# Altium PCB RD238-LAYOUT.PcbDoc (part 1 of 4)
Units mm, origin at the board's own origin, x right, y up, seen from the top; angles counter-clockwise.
Board outline 100 x 120 mm, 4 copper layers (Top Layer, GND2, POWER 3, Bottom Layer), stack 1.444 mm thick; 434 components, 174 nets, 1045 pads, 261 vias.
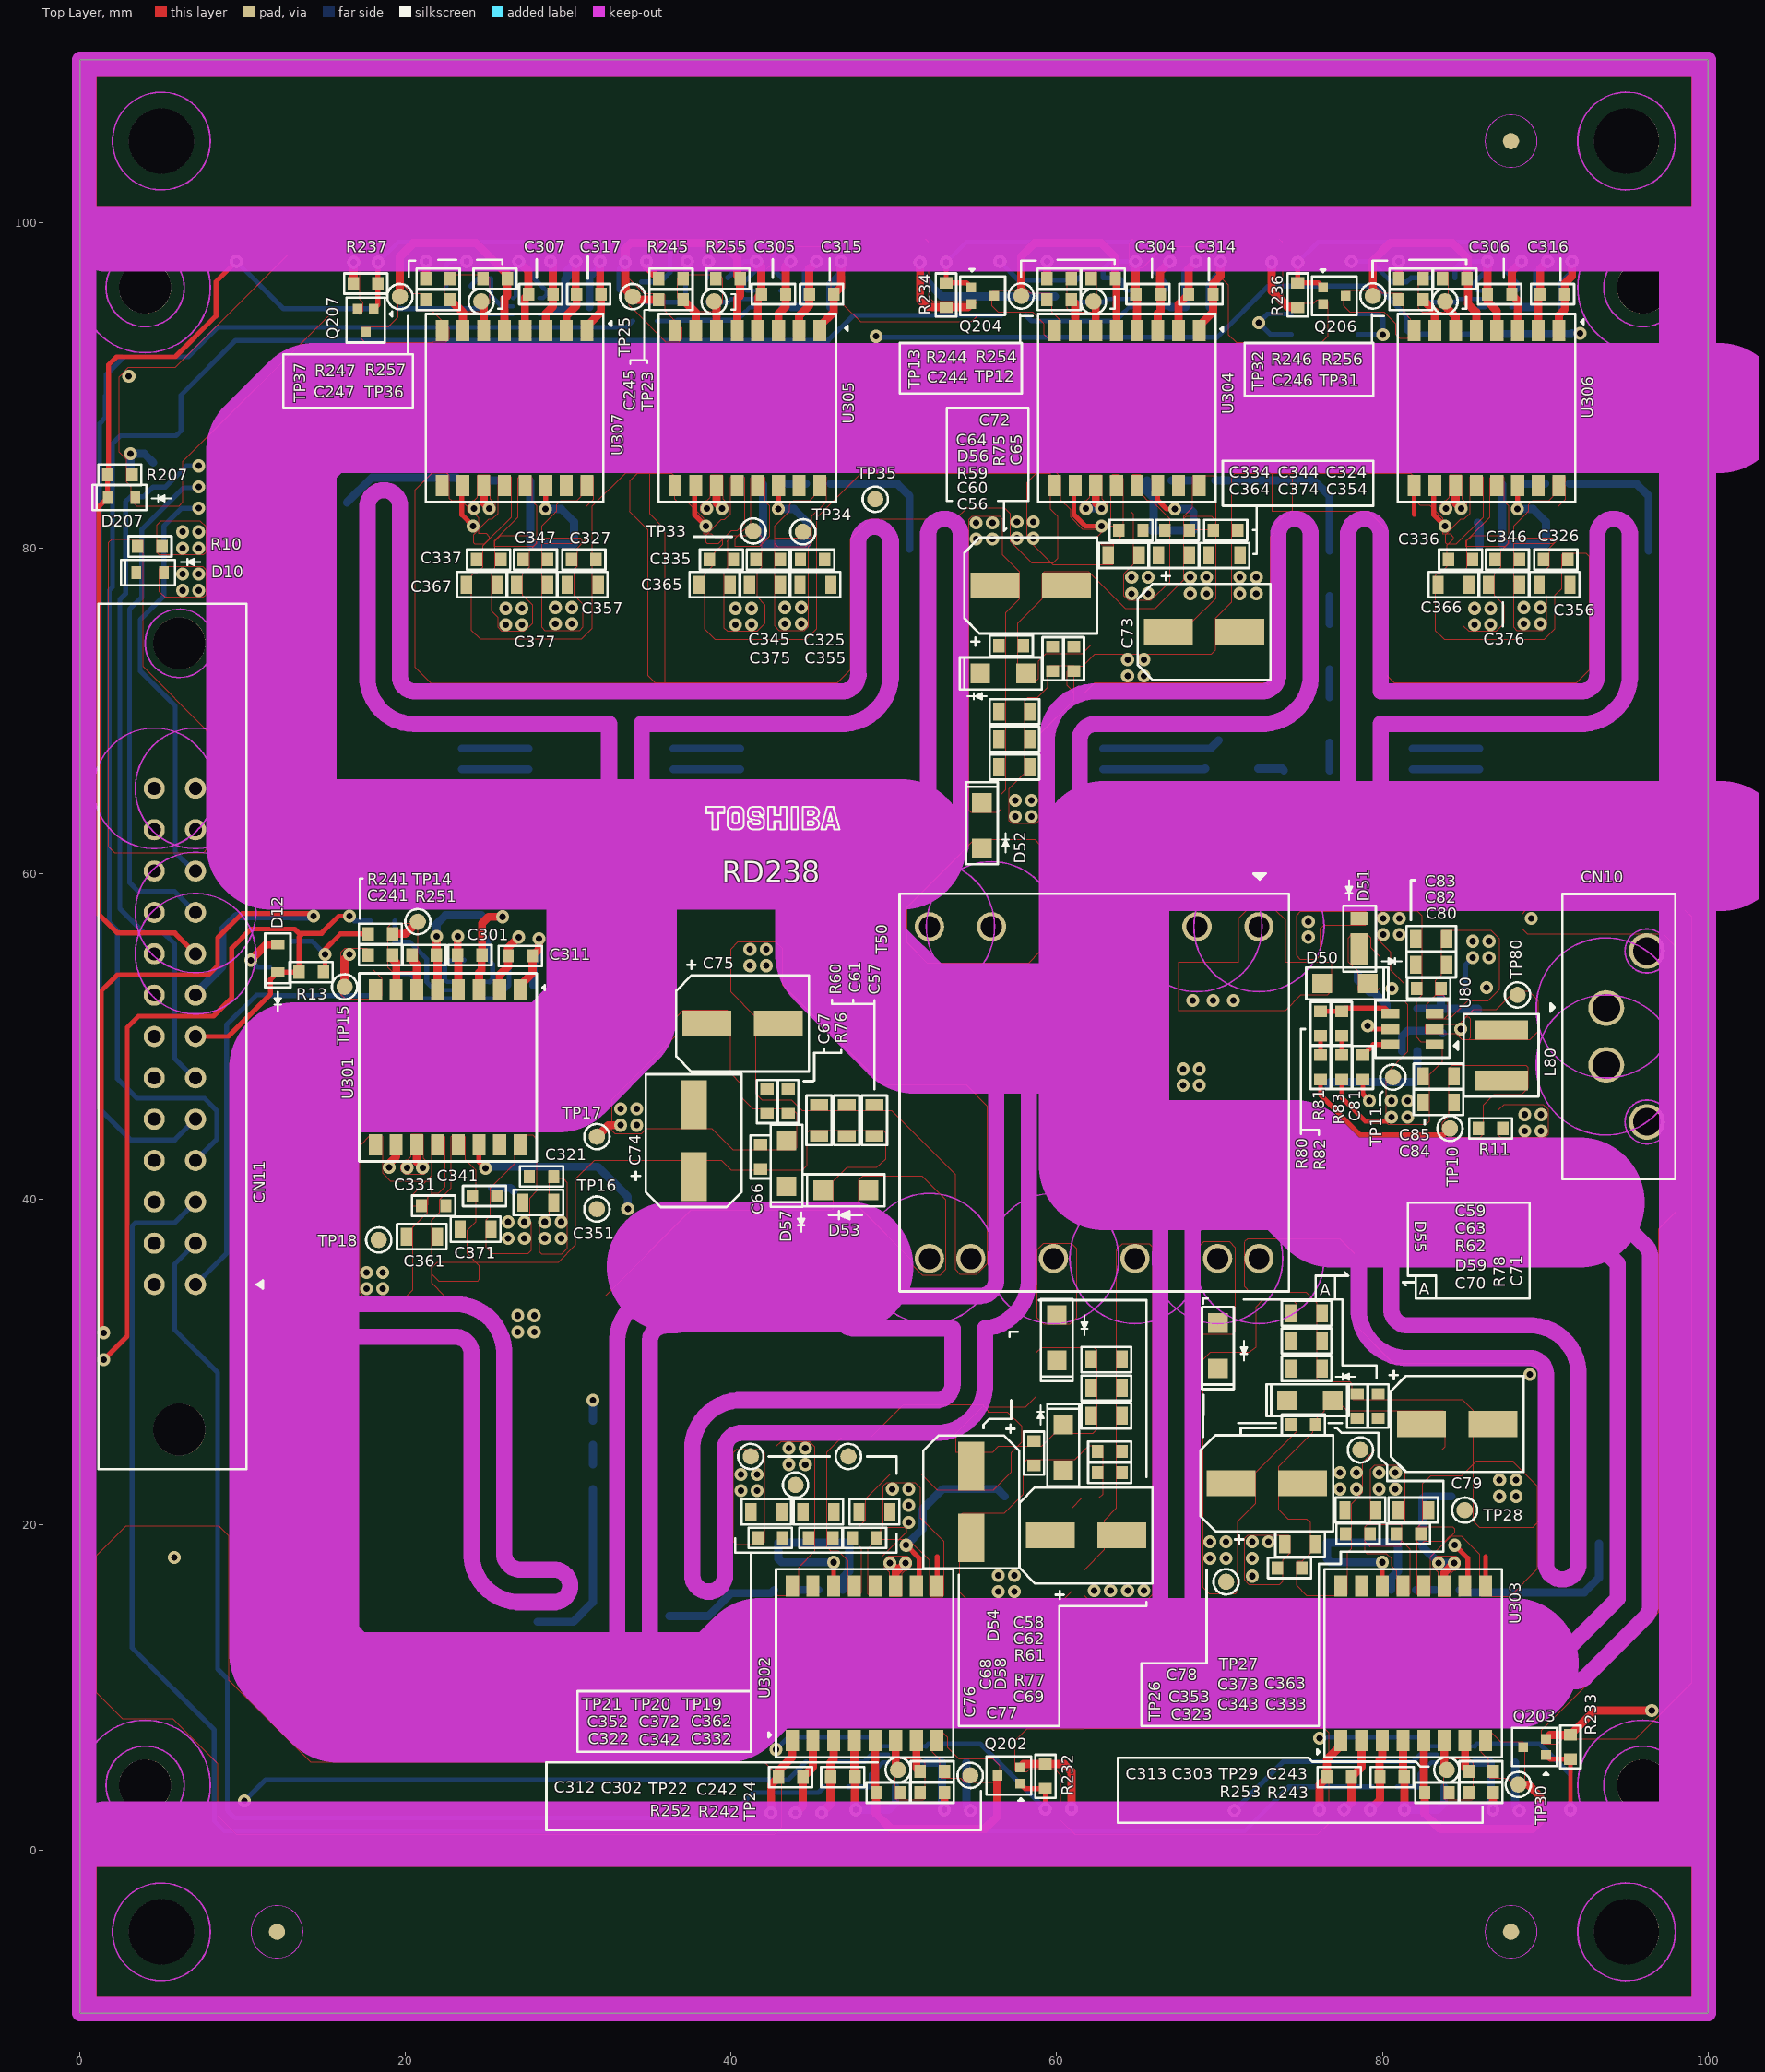
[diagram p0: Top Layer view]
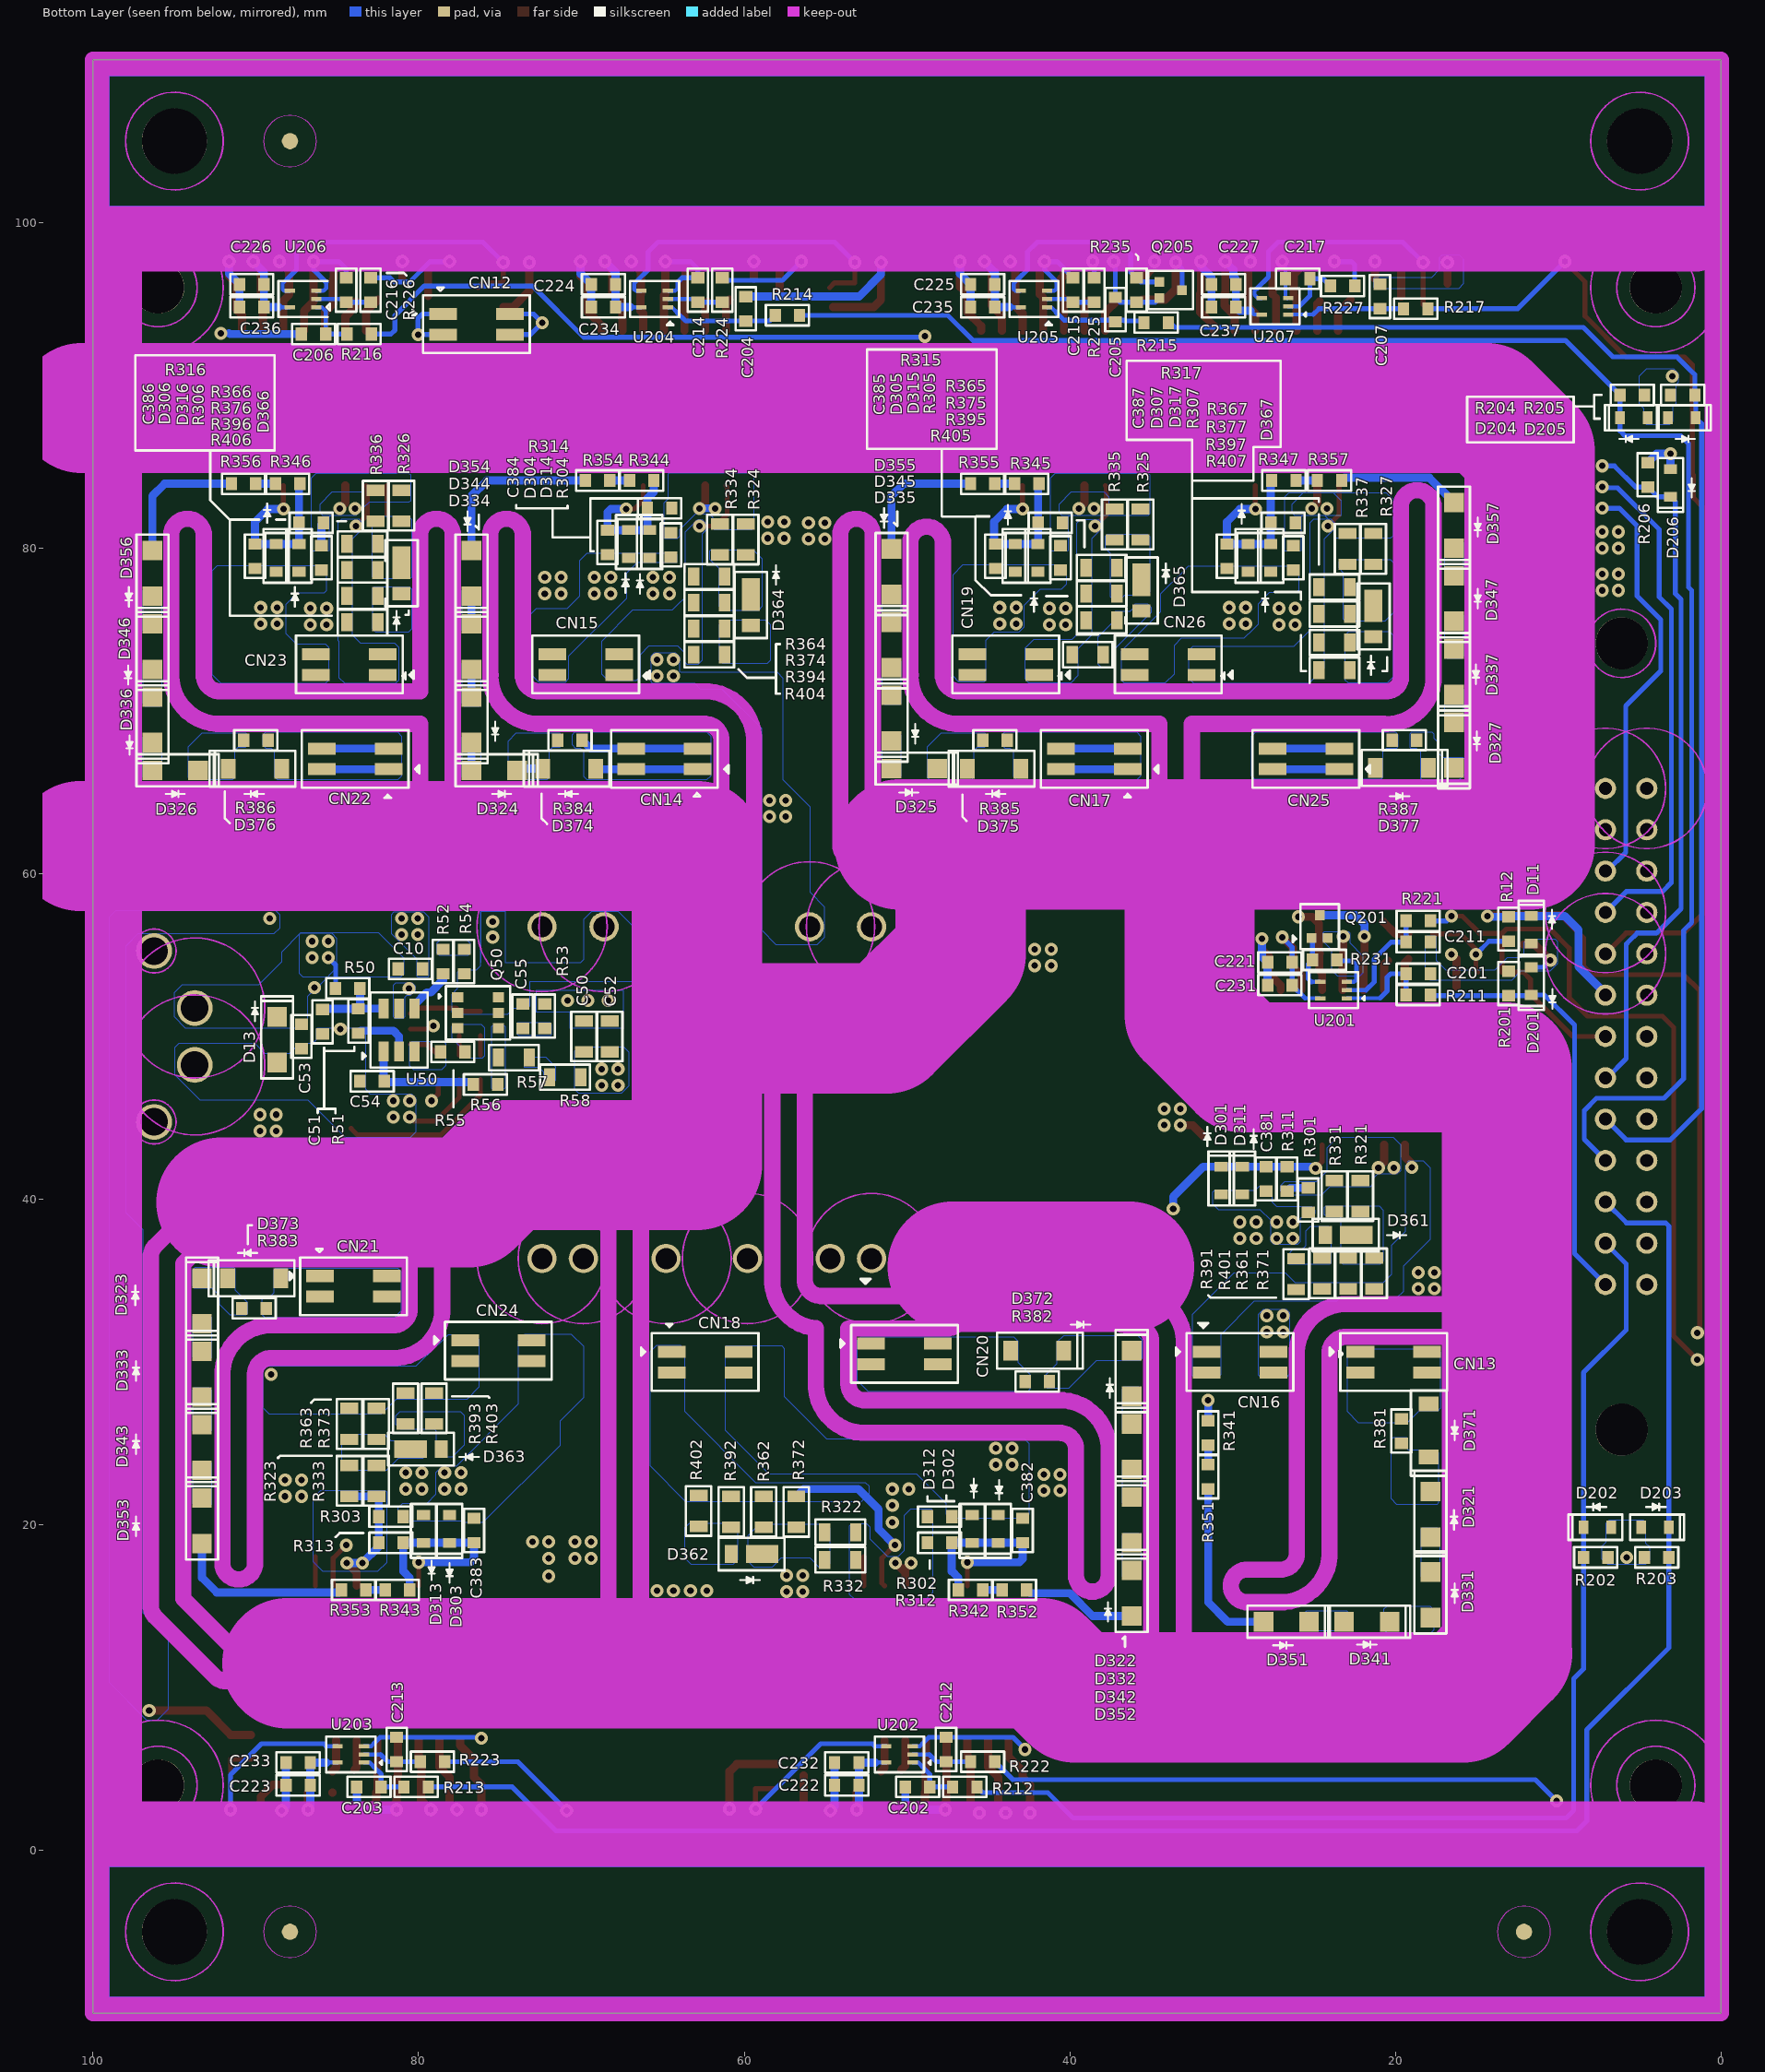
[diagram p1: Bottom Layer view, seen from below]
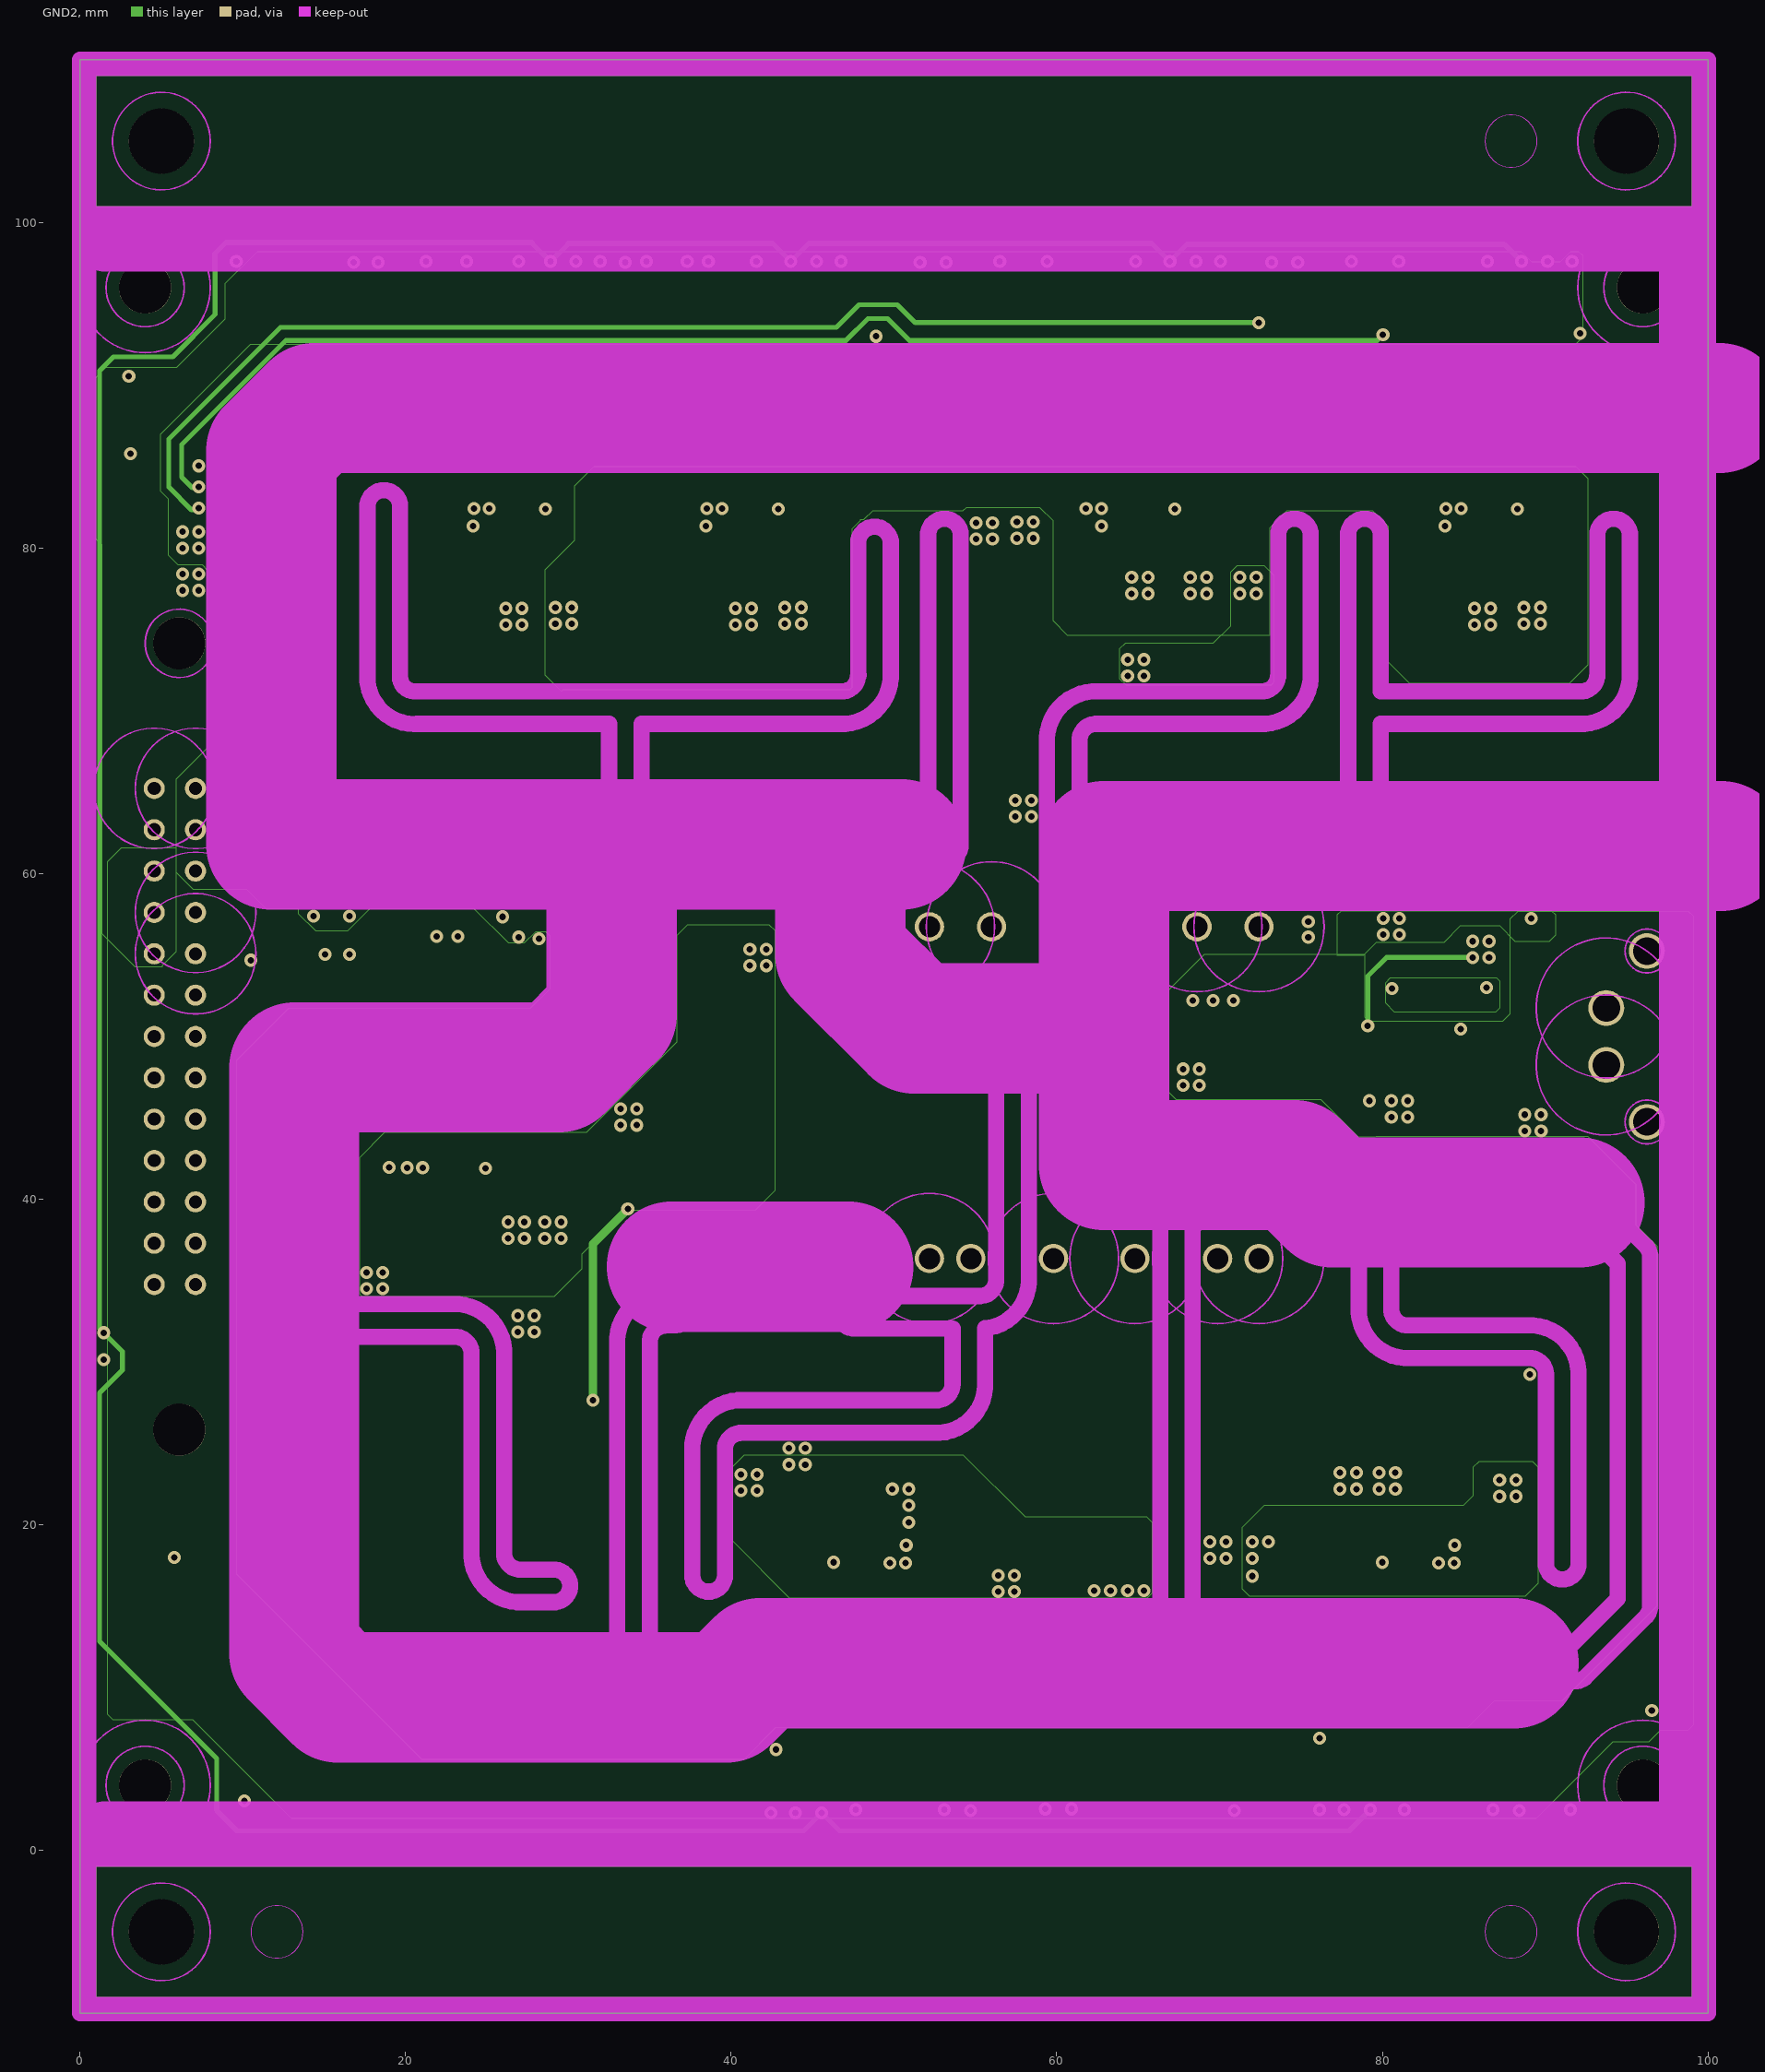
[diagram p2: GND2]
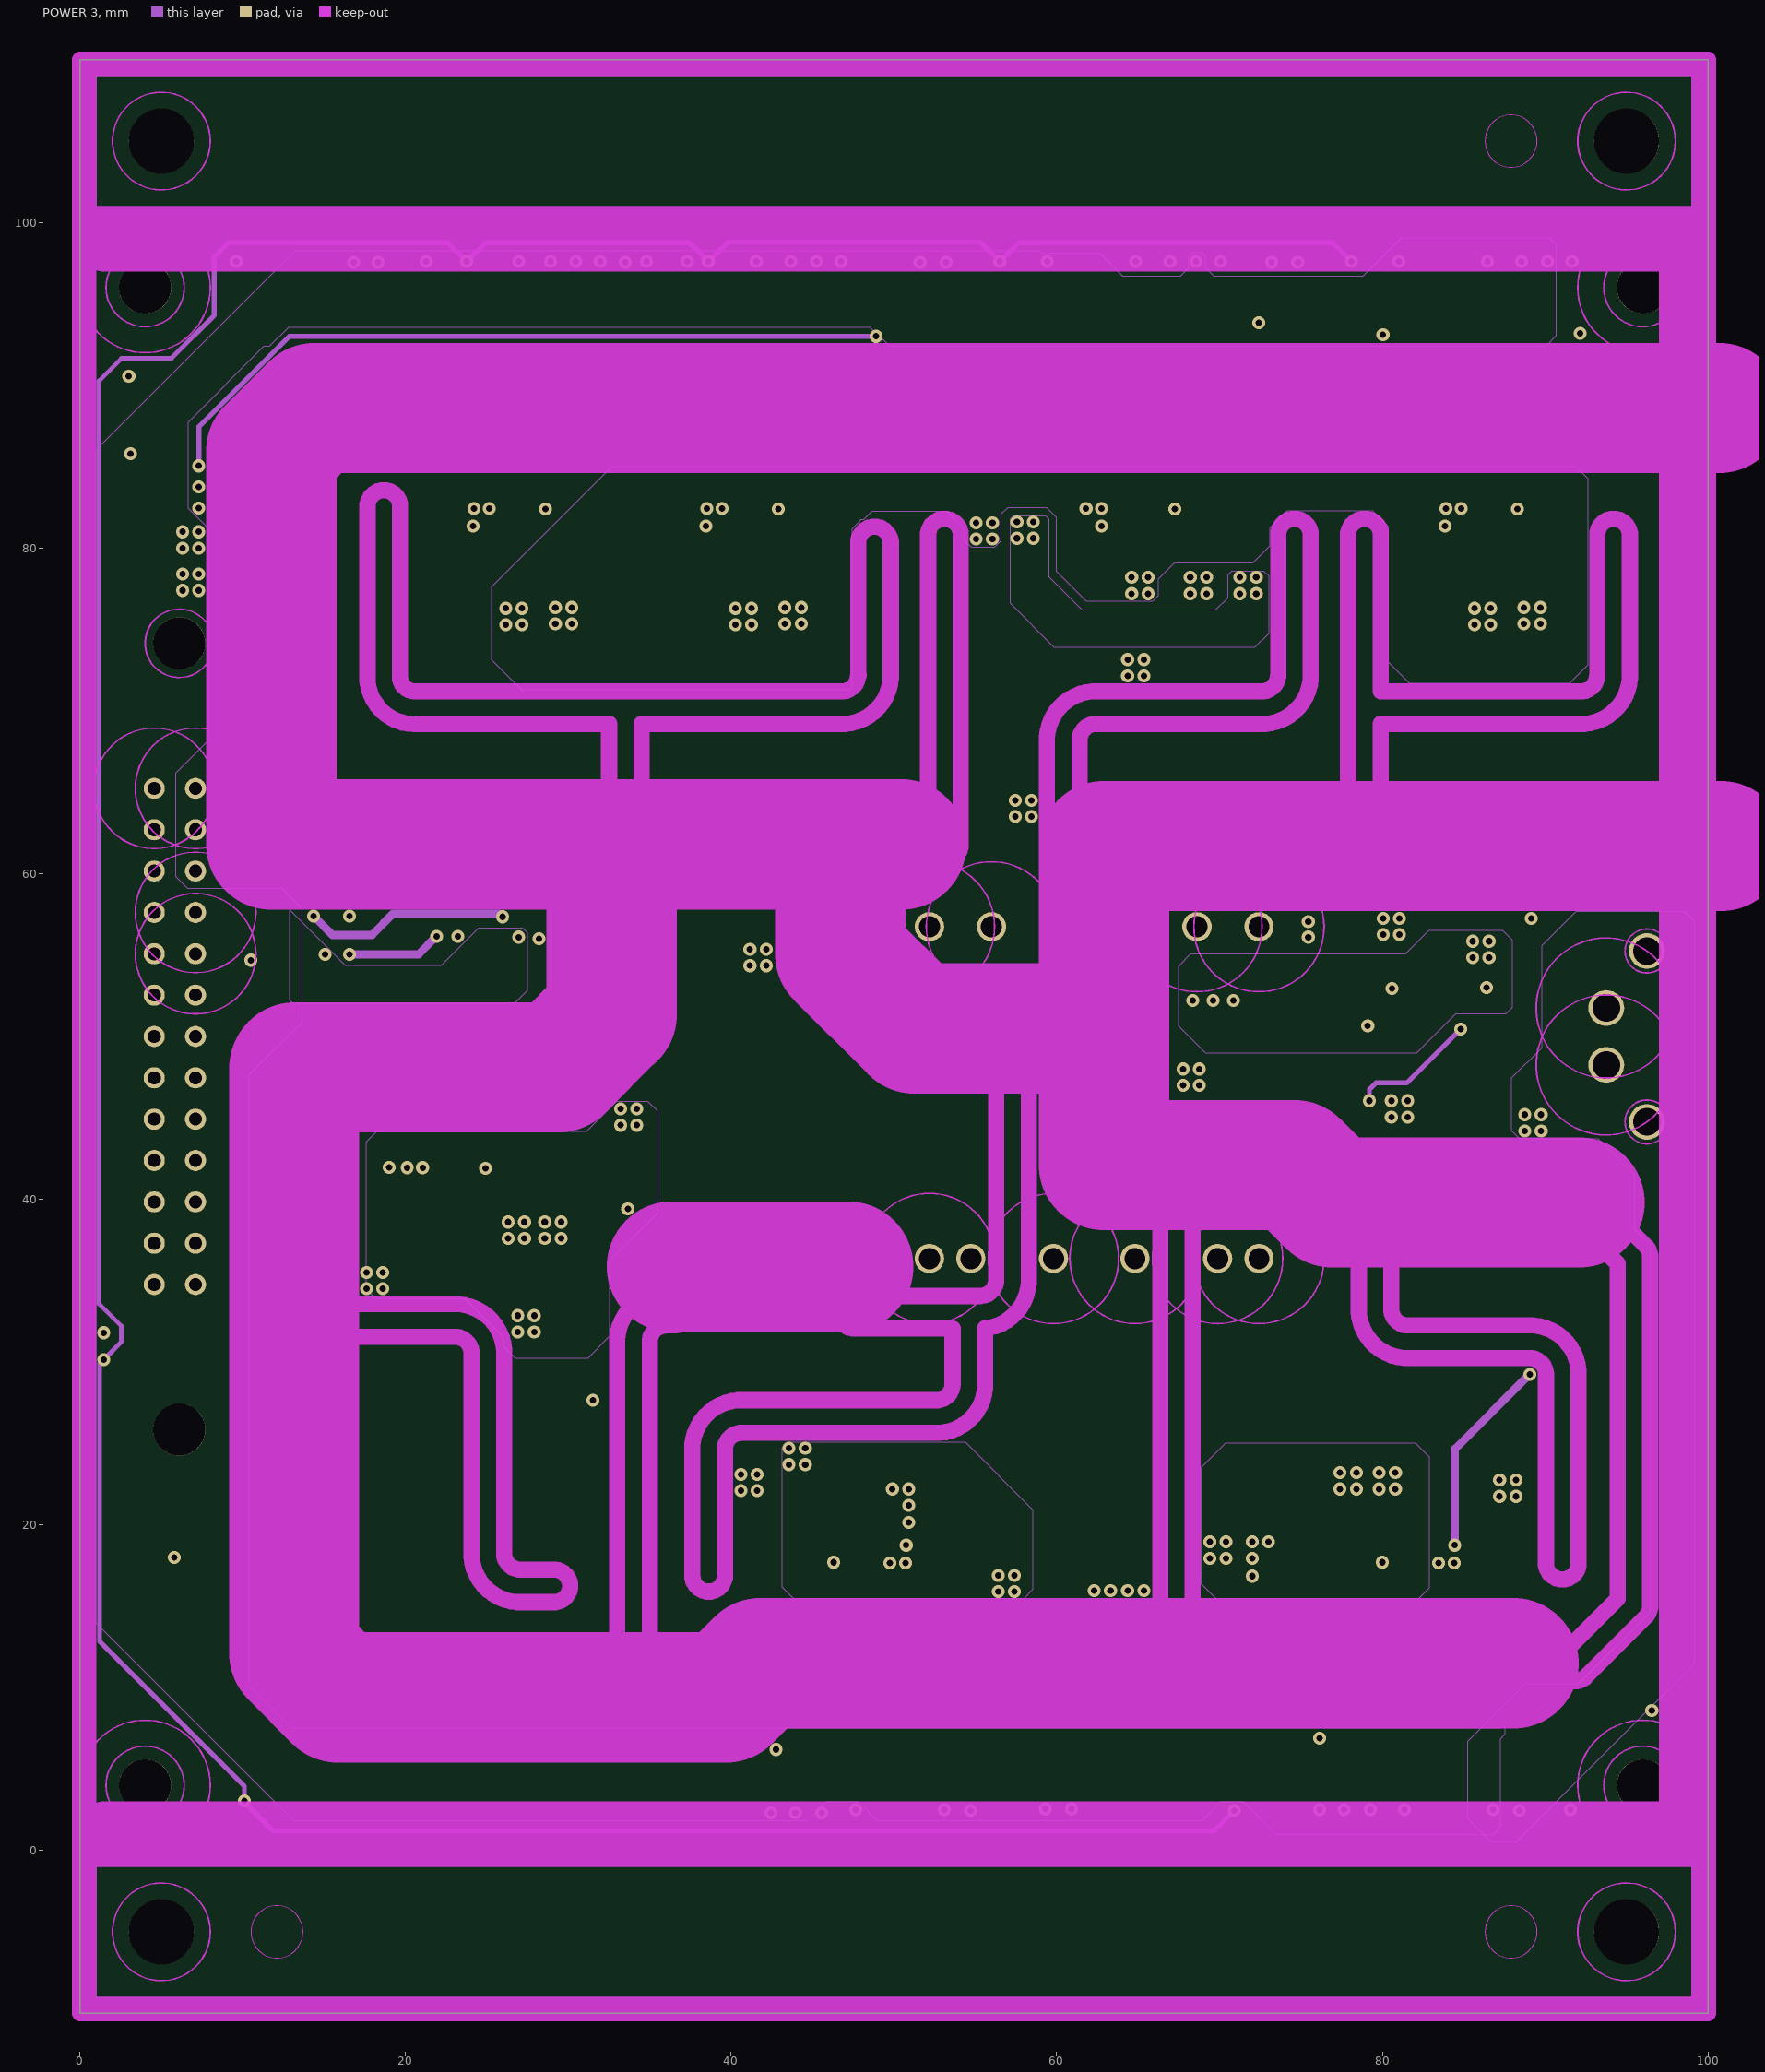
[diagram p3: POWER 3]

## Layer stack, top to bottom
Top Solder: solder mask 0.018, Solder Resist, Dk 3.5
Top Layer: signal copper 0.018
Dielectric 1: dielectric 0.12, FR-4, Dk 4.8
GND2: signal copper 0.035
Dielectric 3: prepreg 0.609, FR-4, Dk 4.1
POWER 3: signal copper 0.035
Dielectric 2: prepreg 0.609, FR-4, Dk 4.1
Bottom Layer: signal copper 0.018
Bottom Solder: solder mask 0.018, Solder Resist, Dk 3.5

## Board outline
0,-10 0,110 100,110 100,-10

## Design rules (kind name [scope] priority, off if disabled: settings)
AssemblyTestPointUsage [All] p0: scope1count=1 scope1_0_kind=Board scope1_0_value=Board scope2count=1 scope2_0_kind=Board scope2_0_value=Board commentlength=0
AssemblyTestpoint [All] p0: scope1count=1 scope1_0_kind=Board scope1_0_value=Board scope2count=1 scope2_0_kind=Board scope2_0_value=Board commentlength=0
Clearance Clearance_R [All] p0 off: scope1count=1 scope1_0_kind=Board scope1_0_value=Board scope2count=1 scope2_0_kind=Board scope2_0_value=Board commentlength=59 gap=0.15 // Protel DXP Scope 1 Expression Was: WithinRoom('ROOM-R')
Clearance Clearance_U200-C [All] p0 off: scope1count=1 scope1_0_kind=Board scope1_0_value=Board scope2count=1 scope2_0_kind=Board scope2_0_value=Board commentlength=64 gap=0.15 // Protel DXP Scope 1 Expression Was: WithinRoom('Room-U200-C')
Clearance Clearance_U200-B [All] p0 off: scope1count=1 scope1_0_kind=Board scope1_0_value=Board scope2count=1 scope2_0_kind=Board scope2_0_value=Board commentlength=64 gap=0.15 // Protel DXP Scope 1 Expression Was: WithinRoom('Room-U200-B')
Clearance Clearance_U200-A [All] p0 off: scope1count=1 scope1_0_kind=Board scope1_0_value=Board scope2count=1 scope2_0_kind=Board scope2_0_value=Board commentlength=64 gap=0.15 // Protel DXP Scope 1 Expression Was: WithinRoom('Room-U200-A')
Clearance Clearance_U200-F [All] p0 off: scope1count=1 scope1_0_kind=Board scope1_0_value=Board scope2count=1 scope2_0_kind=Board scope2_0_value=Board commentlength=64 gap=0.15 // Protel DXP Scope 1 Expression Was: WithinRoom('Room-U200-F')
Clearance Clearance_U200-D [All] p0 off: scope1count=1 scope1_0_kind=Board scope1_0_value=Board scope2count=1 scope2_0_kind=Board scope2_0_value=Board commentlength=64 gap=0.15 // Protel DXP Scope 1 Expression Was: WithinRoom('Room-U200-D')
Clearance Clearance_0.3_2 [All] p0 off: scope1count=1 scope1_0_kind=Board scope1_0_value=Board scope2count=1 scope2_0_kind=Board scope2_0_value=Board commentlength=63 gap=0.5 // Protel DXP Scope 2 Expression Was: WithinRoom('Room-0.3-1')
Clearance Clearance_U200-E [All] p0 off: scope1count=1 scope1_0_kind=Board scope1_0_value=Board scope2count=1 scope2_0_kind=Board scope2_0_value=Board commentlength=64 gap=0.15 // Protel DXP Scope 1 Expression Was: WithinRoom('Room-U200-E')
Clearance Clearance_U200-G [All] p0 off: scope1count=1 scope1_0_kind=Board scope1_0_value=Board scope2count=1 scope2_0_kind=Board scope2_0_value=Board commentlength=64 gap=0.15 // Protel DXP Scope 1 Expression Was: WithinRoom('Room-U200-G')
Clearance Clearance_0.3 [All] p0 off: scope1count=1 scope1_0_kind=Board scope1_0_value=Board scope2count=1 scope2_0_kind=Board scope2_0_value=Board commentlength=61 gap=0.5 // Protel DXP Scope 2 Expression Was: WithinRoom('Room-0.3')
Clearance Clearance_U500 [All] p0 off: scope1count=1 scope1_0_kind=Board scope1_0_value=Board scope2count=1 scope2_0_kind=Board scope2_0_value=Board commentlength=62 gap=0.15 // Protel DXP Scope 1 Expression Was: WithinRoom('Room-U500')
Clearance Clearance_U300-N_6 [All] p0 off: scope1count=1 scope1_0_kind=Board scope1_0_value=Board scope2count=1 scope2_0_kind=Board scope2_0_value=Board commentlength=66 gap=0.15 // Protel DXP Scope 1 Expression Was: WithinRoom('Room-U300_N_6')
Clearance Clearance_U300-N_5 [All] p0 off: scope1count=1 scope1_0_kind=Board scope1_0_value=Board scope2count=1 scope2_0_kind=Board scope2_0_value=Board commentlength=66 gap=0.15 // Protel DXP Scope 1 Expression Was: WithinRoom('Room-U300_N_5')
Clearance Clearance_U300-N_4 [All] p0 off: scope1count=1 scope1_0_kind=Board scope1_0_value=Board scope2count=1 scope2_0_kind=Board scope2_0_value=Board commentlength=66 gap=0.15 // Protel DXP Scope 1 Expression Was: WithinRoom('Room-U300_N_4')
Clearance Clearance_U300-N_3 [All] p0 off: scope1count=1 scope1_0_kind=Board scope1_0_value=Board scope2count=1 scope2_0_kind=Board scope2_0_value=Board commentlength=66 gap=0.15 // Protel DXP Scope 1 Expression Was: WithinRoom('Room-U300_N_3')
Clearance Clearance_U300-N_2 [All] p0 off: scope1count=1 scope1_0_kind=Board scope1_0_value=Board scope2count=1 scope2_0_kind=Board scope2_0_value=Board commentlength=66 gap=0.15 // Protel DXP Scope 1 Expression Was: WithinRoom('Room-U300_N_2')
Clearance Clearance_U300-N_1 [All] p0 off: scope1count=1 scope1_0_kind=Board scope1_0_value=Board scope2count=1 scope2_0_kind=Board scope2_0_value=Board commentlength=66 gap=0.15 // Protel DXP Scope 1 Expression Was: WithinRoom('Room-U300_N_1')
Clearance Clearance_U300-N [All] p0 off: scope1count=1 scope1_0_kind=Board scope1_0_value=Board scope2count=1 scope2_0_kind=Board scope2_0_value=Board commentlength=64 gap=0.15 // Protel DXP Scope 1 Expression Was: WithinRoom('Room-U300_N')
Clearance [All] p0 off: scope1count=1 scope1_0_kind=Board scope1_0_value=Board scope2count=1 scope2_0_kind=Board scope2_0_value=Board commentlength=63 gap=0.5 // Protel DXP Scope 2 Expression Was: (InNetClass('All Nets'))
Clearance polygon [All] p0: scope1count=1 scope1_0_kind=Board scope1_0_value=Board scope2count=1 scope2_0_kind=Layer scope2_0_value=TOP commentlength=0 gap=0.001
Clearance polygon [All vs OnLayer('Keep-Out Layer')] p1: gap=0.001 ignorepadtopadclearanceinfootprint=TRUE
Clearance Clearance_U300-N [WithinRoom('Room-U300_N')] p2: gap=0.15 ignorepadtopadclearanceinfootprint=TRUE except(0.3: Poly-Poly; 0.5: SMDPad-SMDPad SMDPad-THPad THPad-THPad)
Clearance Clearance_U200-F [WithinRoom('Room-U200-F')] p3: gap=0.15 ignorepadtopadclearanceinfootprint=TRUE except(0.3: Poly-Poly; 0.5: SMDPad-SMDPad SMDPad-THPad THPad-THPad)
Clearance Clearance_U200-A [WithinRoom('Room-U200-A')] p4: gap=0.15 ignorepadtopadclearanceinfootprint=TRUE except(0.3: Poly-Poly; 0.5: SMDPad-SMDPad SMDPad-THPad THPad-THPad)
Clearance Clearance_U200-C [WithinRoom('Room-U200-C')] p5: gap=0.15 ignorepadtopadclearanceinfootprint=TRUE except(0.3: Poly-Poly; 0.5: SMDPad-SMDPad SMDPad-THPad THPad-THPad)
Clearance Clearance_U200-B [WithinRoom('Room-U200-B')] p6: gap=0.15 ignorepadtopadclearanceinfootprint=TRUE except(0.3: Poly-Poly; 0.5: SMDPad-SMDPad SMDPad-THPad THPad-THPad)
Clearance Clearance_U200-D [WithinRoom('Room-U200-D')] p7: gap=0.15 ignorepadtopadclearanceinfootprint=TRUE except(0.3: Poly-Poly; 0.5: SMDPad-SMDPad SMDPad-THPad THPad-THPad)
Clearance Clearance_U200-G [WithinRoom('Room-U200-G')] p8: gap=0.15 ignorepadtopadclearanceinfootprint=TRUE except(0.3: Poly-Poly; 0.5: Track-Poly SMDPad-SMDPad SMDPad-THPad THPad-THPad Via-Poly)
Clearance Clearance_U200-E [WithinRoom('Room-U200-E')] p9: gap=0.15 ignorepadtopadclearanceinfootprint=TRUE except(0.3: Poly-Poly; 0.5: Arc-Poly Track-Poly SMDPad-SMDPad SMDPad-THPad THPad-THPad Via-Poly)
Clearance Clearance_R [WithinRoom('ROOM-R')] p10: gap=0.15 ignorepadtopadclearanceinfootprint=TRUE except(0.3: Poly-Poly; 0.5: Arc-Poly Track-Poly SMDPad-SMDPad SMDPad-THPad THPad-THPad Via-Poly)
Clearance Clearance_U300-N_1 [WithinRoom('Room-U300_N_1')] p11: gap=0.15 ignorepadtopadclearanceinfootprint=TRUE except(0.3: Poly-Poly; 0.5: SMDPad-SMDPad SMDPad-THPad THPad-THPad)
Clearance Clearance_U300-N_2 [WithinRoom('Room-U300_N_2')] p12: gap=0.15 ignorepadtopadclearanceinfootprint=TRUE except(0.3: Poly-Poly; 0.5: SMDPad-SMDPad SMDPad-THPad THPad-THPad)
Clearance Clearance_U300-N_3 [WithinRoom('Room-U300_N_3')] p13: gap=0.15 ignorepadtopadclearanceinfootprint=TRUE except(0.3: Poly-Poly; 0.5: SMDPad-SMDPad SMDPad-THPad THPad-THPad)
Clearance Clearance_U300-N_4 [WithinRoom('Room-U300_N_4')] p14: gap=0.15 ignorepadtopadclearanceinfootprint=TRUE except(0.3: Poly-Poly; 0.5: SMDPad-SMDPad SMDPad-THPad THPad-THPad)
Clearance Clearance_U300-N_5 [WithinRoom('Room-U300_N_5')] p15: gap=0.15 ignorepadtopadclearanceinfootprint=TRUE except(0.3: Poly-Poly; 0.5: SMDPad-SMDPad SMDPad-THPad THPad-THPad)
Clearance Clearance_U300-N_6 [WithinRoom('Room-U300_N_6')] p16: gap=0.15 ignorepadtopadclearanceinfootprint=TRUE except(0.3: Poly-Poly; 0.5: SMDPad-SMDPad SMDPad-THPad THPad-THPad)
Clearance Clearance_U500 [WithinRoom('Room-U500')] p17: gap=0.15 ignorepadtopadclearanceinfootprint=TRUE except(0.3: Via-Poly Poly-Poly; 0.5: SMDPad-SMDPad SMDPad-THPad THPad-THPad)
Clearance Clearance_0.3 [All vs WithinRoom('Room-0.3')] p18: gap=0.5 ignorepadtopadclearanceinfootprint=TRUE except(0: Arc-Hole Track-Hole SMDPad-Hole THPad-Hole Via-Hole Fill-Poly Fill-Hole Poly-Hole Region-Hole Text-Hole; 0.1: Poly-Text; 0.25: SMDPad-Fill SMDPad-Region SMDPad-Text; 0.254: THPad-Region THPad-Text Region-Region Region-Text Text-Text; 0.3: Arc-Track Track-Track; 0.45: Track-THPad Track-Region Track-Text THPad-Fill THPad-Poly Via-Via Via-Fill Via-Region Via-Text Fill-Fill Fill-Region Fill-Text Poly-Region)
Clearance Clearance_0.3_2 [All vs WithinRoom('Room-0.3-1')] p19: gap=0.5 ignorepadtopadclearanceinfootprint=TRUE except(0: Arc-Hole Track-Hole SMDPad-Hole THPad-Hole Via-Hole Fill-Poly Fill-Hole Poly-Hole Region-Hole Text-Hole; 0.1: Poly-Text; 0.25: SMDPad-Fill SMDPad-Region SMDPad-Text; 0.254: THPad-Region THPad-Text Region-Region Region-Text Text-Text; 0.3: Arc-Track Track-Track; 0.45: Track-THPad Track-Region Track-Text THPad-Fill THPad-Poly Via-Via Via-Fill Via-Region Via-Text Fill-Fill Fill-Region Fill-Text Poly-Region)
Clearance [All vs (InNetClass('All Nets'))] p20: gap=0.5 ignorepadtopadclearanceinfootprint=TRUE except(0: Arc-Hole Track-Hole SMDPad-Hole THPad-Hole Via-Hole Fill-Poly Fill-Hole Poly-Hole Region-Hole Text-Hole; 0.1: Poly-Text; 0.25: SMDPad-Fill SMDPad-Region SMDPad-Text; 0.254: THPad-Region THPad-Text Region-Region Region-Text Text-Text; 0.45: Track-THPad Track-Region Track-Text THPad-Fill THPad-Poly Via-Via Via-Fill Via-Region Via-Text Fill-Fill Fill-Region Fill-Text Poly-Region)
ComponentClearance [All] p0: scope1count=1 scope1_0_kind=Board scope1_0_value=Board scope2count=1 scope2_0_kind=Board scope2_0_value=Board commentlength=0 gap=0.254 collisioncheckmode=3
DiffPairsRouting [All] p0: scope1count=1 scope1_0_kind=Board scope1_0_value=Board scope2count=1 scope2_0_kind=Board scope2_0_value=Board commentlength=0
FabricationTestPointUsage [All] p0: scope1count=1 scope1_0_kind=Board scope1_0_value=Board scope2count=1 scope2_0_kind=Board scope2_0_value=Board commentlength=0 valid=0 allowmultiple=FALSE
FabricationTestpoint [All] p0: scope1count=1 scope1_0_kind=Board scope1_0_value=Board scope2count=1 scope2_0_kind=Board scope2_0_value=Board commentlength=0 side=3 testpointundercomponent=TRUE minsize=1.016 maxsize=2.54 preferedsize=1.524 minholesize=0 maxholesize=1.016 preferedholesize=0.813 testpointgrid=0.025
FanoutControl Fanout_BGA [All] p0 off: scope1count=1 scope1_0_kind=Board scope1_0_value=Board scope2count=1 scope2_0_kind=Board scope2_0_value=Board commentlength=69 // Protel DXP Scope 1 Expression Was: IsBGA   Fanout_BGA (Default Rule)
FanoutControl Fanout_LCC [All] p0 off: scope1count=1 scope1_0_kind=Board scope1_0_value=Board scope2count=1 scope2_0_kind=Board scope2_0_value=Board commentlength=69 // Protel DXP Scope 1 Expression Was: IsLCC   Fanout_LCC (Default Rule)
FanoutControl Fanout_SOIC [All] p0 off: scope1count=1 scope1_0_kind=Board scope1_0_value=Board scope2count=1 scope2_0_kind=Board scope2_0_value=Board commentlength=71 // Protel DXP Scope 1 Expression Was: IsSOIC   Fanout_SOIC (Default Rule)
FanoutControl Fanout_Small [All] p0 off: scope1count=1 scope1_0_kind=Board scope1_0_value=Board scope2count=1 scope2_0_kind=Board scope2_0_value=Board commentlength=84 // Protel DXP Scope 1 Expression Was: (CompPinCount < 5)   Fanout_Small (Default Rule)
FanoutControl Fanout_Default [All] p0: scope1count=1 scope1_0_kind=Board scope1_0_value=Board scope2count=1 scope2_0_kind=Board scope2_0_value=Board commentlength=30 // Fanout_Default (Default Rule)
Height Height_1 [All] p0: scope1count=1 scope1_0_kind=ComponentClass scope1_0_value="Bottom Side Components" scope2count=1 scope2_0_kind=Board scope2_0_value=Board commentlength=0
Height [All] p0: scope1count=1 scope1_0_kind=Board scope1_0_value=Board scope2count=1 scope2_0_kind=Board scope2_0_value=Board commentlength=0
Height Height_1 [InComponentClass('Bottom Side Components')] p1: minheight=0 maxheight=2.5 prefheight=2.5
Height [All] p2: minheight=0 maxheight=50 prefheight=12.7
HoleSize [All] p0 off: scope1count=1 scope1_0_kind=Board scope1_0_value=Board scope2count=1 scope2_0_kind=Board scope2_0_value=Board commentlength=44 absolutevalues=TRUE maxlimit=0.4 minlimit=0.4 maxpercent=80.000 minpercent=20.000 // Protel DXP Scope 1 Expression Was: IsVia
HoleSize [IsVia] p1: absolutevalues=TRUE maxlimit=0.4 minlimit=0.4 maxpercent=80.000 minpercent=20.000
HoleToHoleClearance [All] p0: scope1count=1 scope1_0_kind=Board scope1_0_value=Board scope2count=1 scope2_0_kind=Board scope2_0_value=Board commentlength=0
LayerPairs [All] p0: scope1count=1 scope1_0_kind=Board scope1_0_value=Board scope2count=1 scope2_0_kind=Board scope2_0_value=Board commentlength=0 enforce=TRUE
MinimumSolderMaskSliver [All] p0: scope1count=1 scope1_0_kind=Board scope1_0_value=Board scope2count=1 scope2_0_kind=Board scope2_0_value=Board commentlength=0
MinimumSolderMaskSliver [All] p1: minsoldermaskwidth=0.1
NetAntennae [All] p0: scope1count=1 scope1_0_kind=Board scope1_0_value=Board scope2count=1 scope2_0_kind=Board scope2_0_value=Board commentlength=0
PasteMaskExpansion [All] p0: scope1count=1 scope1_0_kind=Board scope1_0_value=Board scope2count=1 scope2_0_kind=Board scope2_0_value=Board commentlength=0 expansion=0
PlaneClearance [All] p0: scope1count=1 scope1_0_kind=Board scope1_0_value=Board scope2count=1 scope2_0_kind=Board scope2_0_value=Board commentlength=0 clearance=0.508
PlaneConnect [All] p0: scope1count=1 scope1_0_kind=Board scope1_0_value=Board scope2count=1 scope2_0_kind=Board scope2_0_value=Board commentlength=0 planeconnectstyle=Relief reliefexpansion=0.508 reliefentries=4 reliefconductorwidth=0.254 reliefairgap=0.254
PolygonConnect PolygonConnect_g [All] p0 off: scope1count=1 scope1_0_kind=Board scope1_0_value=Board scope2count=1 scope2_0_kind=Board scope2_0_value=Board commentlength=44 connectstyle=Direct reliefconductorwidth=0.254 reliefentries=4 polygonreliefangle="90 Angle" // Protel DXP Scope 1 Expression Was: IsVia
PolygonConnect PolygonConnect_H [All] p0: scope1count=1 scope1_0_kind=Footprint scope1_0_value=XG4A-1431 scope2count=1 scope2_0_kind=Board scope2_0_value=Board commentlength=0 connectstyle=Relief reliefconductorwidth=0.5 reliefentries=4 polygonreliefangle="90 Angle"
PolygonConnect [All] p0: scope1count=1 scope1_0_kind=Board scope1_0_value=Board scope2count=1 scope2_0_kind=Board scope2_0_value=Board commentlength=0 connectstyle=Direct reliefconductorwidth=0.254 reliefentries=4 polygonreliefangle="90 Angle"
PolygonConnect PolygonConnect_g [IsVia] p1: connectstyle=Direct reliefconductorwidth=0.254 reliefentries=4 polygonreliefangle="90 Angle" airgapwidth=0.254
PolygonConnect PolygonConnect_H [HasFootprint('XG4A-1431')] p2: connectstyle=Relief reliefconductorwidth=0.5 reliefentries=4 polygonreliefangle="90 Angle" airgapwidth=0.2
PolygonConnect [All] p3: connectstyle=Direct reliefconductorwidth=0.254 reliefentries=4 polygonreliefangle="90 Angle" airgapwidth=0.254
RoomDefinition ROOM-R [All] p0 off: scope1count=1 scope1_0_kind=Board scope1_0_value=Board scope2count=1 scope2_0_kind=Board scope2_0_value=Board commentlength=44 region_x1=34573228 region_y1=44090157 region_x2=37053544 region_y2=46609841 confinementstyle=ConfineIn // Protel DXP Scope 1 Expression Was: False
RoomDefinition Room-U200-C [All] p0 off: scope1count=1 scope1_0_kind=Board scope1_0_value=Board scope2count=1 scope2_0_kind=Board scope2_0_value=Board commentlength=44 region_x1=53638190 region_y1=17889370 region_x2=54356694 region_y2=18794882 confinementstyle=ConfineIn // Protel DXP Scope 1 Expression Was: False
RoomDefinition Room-U200-B [All] p0 off: scope1count=1 scope1_0_kind=Board scope1_0_value=Board scope2count=1 scope2_0_kind=Board scope2_0_value=Board commentlength=44 region_x1=40370472 region_y1=17889370 region_x2=41010237 region_y2=18696457 confinementstyle=ConfineIn // Protel DXP Scope 1 Expression Was: False
RoomDefinition Room-U200-A [All] p0 off: scope1count=1 scope1_0_kind=Board scope1_0_value=Board scope2count=1 scope2_0_kind=Board scope2_0_value=Board commentlength=44 region_x1=29553544 region_y1=36412992 region_x2=30537796 region_y2=37121653 confinementstyle=ConfineIn // Protel DXP Scope 1 Expression Was: False
RoomDefinition Room-U200-F [All] p0 off: scope1count=1 scope1_0_kind=Board scope1_0_value=Board scope2count=1 scope2_0_kind=Board scope2_0_value=Board commentlength=44 region_x1=54713248 region_y1=52869685 region_x2=55709520 region_y2=53893307 confinementstyle=ConfineIn // Protel DXP Scope 1 Expression Was: False
RoomDefinition Room-U200-D [All] p0 off: scope1count=1 scope1_0_kind=Board scope1_0_value=Board scope2count=1 scope2_0_kind=Board scope2_0_value=Board commentlength=44 region_x1=46325198 region_y1=52968110 region_x2=47014174 region_y2=54050787 confinementstyle=ConfineIn // Protel DXP Scope 1 Expression Was: False
RoomDefinition Room-U200-E [All] p0 off: scope1count=1 scope1_0_kind=Board scope1_0_value=Board scope2count=1 scope2_0_kind=Board scope2_0_value=Board commentlength=44 region_x1=35380316 region_y1=52909055 region_x2=38722372 region_y2=54838189 confinementstyle=ConfineIn // Protel DXP Scope 1 Expression Was: False
RoomDefinition Room-U200-G [All] p0 off: scope1count=1 scope1_0_kind=Board scope1_0_value=Board scope2count=1 scope2_0_kind=Board scope2_0_value=Board commentlength=44 region_x1=31029922 region_y1=52731890 region_x2=32900001 region_y2=54720079 confinementstyle=ConfineIn // Protel DXP Scope 1 Expression Was: False
RoomDefinition Room-0.3-1 [All] p0 off: scope1count=1 scope1_0_kind=Board scope1_0_value=Board scope2count=1 scope2_0_kind=Board scope2_0_value=Board commentlength=44 region_x1=23529922 region_y1=32515354 region_x2=25025985 region_y2=34306693 confinementstyle=ConfineIn // Protel DXP Scope 1 Expression Was: False
RoomDefinition Room-0.3 [All] p0 off: scope1count=1 scope1_0_kind=Board scope1_0_value=Board scope2count=1 scope2_0_kind=Board scope2_0_value=Board commentlength=44 region_x1=21522048 region_y1=37554724 region_x2=23529922 region_y2=46609842 confinementstyle=ConfineIn // Protel DXP Scope 1 Expression Was: False
RoomDefinition Room-U500 [All] p0 off: scope1count=1 scope1_0_kind=Board scope1_0_value=Board scope2count=1 scope2_0_kind=Board scope2_0_value=Board commentlength=44 region_x1=51305513 region_y1=34296851 region_x2=54927560 region_y2=37101969 confinementstyle=ConfineIn // Protel DXP Scope 1 Expression Was: False
RoomDefinition Room-U300_N_6 [All] p0 off: scope1count=1 scope1_0_kind=Board scope1_0_value=Board scope2count=1 scope2_0_kind=Board scope2_0_value=Board commentlength=44 region_x1=37874015 region_y1=21826378 region_x2=42338976 region_y2=24916929 confinementstyle=ConfineIn // Protel DXP Scope 1 Expression Was: False
RoomDefinition Room-U300_N_5 [All] p0 off: scope1count=1 scope1_0_kind=Board scope1_0_value=Board scope2count=1 scope2_0_kind=Board scope2_0_value=Board commentlength=44 region_x1=51141732 region_y1=21826378 region_x2=55498428 region_y2=23834252 confinementstyle=ConfineIn // Protel DXP Scope 1 Expression Was: False
RoomDefinition Room-U300_N_4 [All] p0 off: scope1count=1 scope1_0_kind=Board scope1_0_value=Board scope2count=1 scope2_0_kind=Board scope2_0_value=Board commentlength=44 region_x1=28254331 region_y1=31511417 region_x2=32611027 region_y2=33519291 confinementstyle=ConfineIn // Protel DXP Scope 1 Expression Was: False
RoomDefinition Room-U300_N_1 [All] p0 off: scope1count=1 scope1_0_kind=Board scope1_0_value=Board scope2count=1 scope2_0_kind=Board scope2_0_value=Board commentlength=44 region_x1=44671654 region_y1=47456299 region_x2=49028349 region_y2=49464173 confinementstyle=ConfineIn // Protel DXP Scope 1 Expression Was: False
RoomDefinition Room-U300_N_3 [All] p0 off: scope1count=1 scope1_0_kind=Board scope1_0_value=Board scope2count=1 scope2_0_kind=Board scope2_0_value=Board commentlength=44 region_x1=29868502 region_y1=47456299 region_x2=34225197 region_y2=49464173 confinementstyle=ConfineIn // Protel DXP Scope 1 Expression Was: False
RoomDefinition Room-U300_N_2 [All] p0 off: scope1count=1 scope1_0_kind=Board scope1_0_value=Board scope2count=1 scope2_0_kind=Board scope2_0_value=Board commentlength=44 region_x1=35301573 region_y1=47456299 region_x2=39658268 region_y2=49464173 confinementstyle=ConfineIn // Protel DXP Scope 1 Expression Was: False
RoomDefinition Room-U300_N [All] p0 off: scope1count=1 scope1_0_kind=Board scope1_0_value=Board scope2count=1 scope2_0_kind=Board scope2_0_value=Board commentlength=44 region_x1=53175591 region_y1=47456299 region_x2=57532286 region_y2=49464173 confinementstyle=ConfineIn // Protel DXP Scope 1 Expression Was: False
RoomDefinition ROOM-R [False vs False] p1: confinementstyle=ConfineIn formatcopy=TRUE lockcomponents=FALSE outline 33.7,77.9 40,77.9 40,71.5 33.7,71.5
RoomDefinition Room-U200-C [False vs False] p2: confinementstyle=ConfineIn formatcopy=TRUE lockcomponents=FALSE outline 82.125,7.25 83.95,7.25 83.95,4.95 82.125,4.95
RoomDefinition Room-U200-B [False vs False] p3: confinementstyle=ConfineIn formatcopy=TRUE lockcomponents=FALSE outline 48.425,7 50.05,7 50.05,4.95 48.425,4.95
RoomDefinition Room-U200-A [False vs False] p4: confinementstyle=ConfineIn formatcopy=TRUE lockcomponents=FALSE outline 20.95,53.8 23.45,53.8 23.45,52 20.95,52
RoomDefinition Room-U200-F [False vs False] p5: confinementstyle=ConfineIn formatcopy=TRUE lockcomponents=FALSE outline 84.856,96.4 87.386,96.4 87.386,93.8 84.856,93.8
RoomDefinition Room-U200-D [False vs False] p6: confinementstyle=ConfineIn formatcopy=TRUE lockcomponents=FALSE outline 63.55,96.8 65.3,96.8 65.3,94.05 63.55,94.05
RoomDefinition Room-U200-E [False vs False] p7: confinementstyle=ConfineIn formatcopy=TRUE lockcomponents=FALSE outline 35.75,98.8 44.239,98.8 44.239,93.9 35.75,93.9
RoomDefinition Room-U200-G [False vs False] p8: confinementstyle=ConfineIn formatcopy=TRUE lockcomponents=FALSE outline 24.7,98.5 29.45,98.5 29.45,93.45 24.7,93.45
RoomDefinition Room-0.3-1 [False vs False] p9: confinementstyle=ConfineIn formatcopy=TRUE lockcomponents=FALSE outline 5.65,46.65 9.45,46.65 9.45,42.1 5.65,42.1
RoomDefinition Room-0.3 [False vs False] p10: confinementstyle=ConfineIn formatcopy=TRUE lockcomponents=FALSE outline 0.55,77.9 5.65,77.9 5.65,54.9 0.55,54.9
RoomDefinition Room-U500 [False vs False] p11: confinementstyle=ConfineIn formatcopy=TRUE lockcomponents=FALSE outline 76.2,53.75 85.4,53.75 85.4,46.625 76.2,46.625
RoomDefinition Room-U300_N_6 [False vs False] p12: confinementstyle=ConfineIn formatcopy=TRUE lockcomponents=FALSE outline 53.425,14.95 42.084,14.95 42.084,22.8 53.425,22.8
RoomDefinition Room-U300_N_5 [False vs False] p13: confinementstyle=ConfineIn formatcopy=TRUE lockcomponents=FALSE outline 86.85,14.95 75.784,14.95 75.784,20.05 86.85,20.05
RoomDefinition Room-U300_N_4 [False vs False] p14: confinementstyle=ConfineIn formatcopy=TRUE lockcomponents=FALSE outline 17.65,44.65 28.716,44.65 28.716,39.55 17.65,39.55
RoomDefinition Room-U300_N_1 [False vs False] p15: confinementstyle=ConfineIn formatcopy=TRUE lockcomponents=FALSE outline 59.35,85.15 70.416,85.15 70.416,80.05 59.35,80.05
RoomDefinition Room-U300_N_3 [False vs False] p16: confinementstyle=ConfineIn formatcopy=TRUE lockcomponents=FALSE outline 21.75,85.15 32.816,85.15 32.816,80.05 21.75,80.05
RoomDefinition Room-U300_N_2 [False vs False] p17: confinementstyle=ConfineIn formatcopy=TRUE lockcomponents=FALSE outline 35.55,85.15 46.616,85.15 46.616,80.05 35.55,80.05
RoomDefinition Room-U300_N [False vs False] p18: confinementstyle=ConfineIn formatcopy=TRUE lockcomponents=FALSE outline 80.95,85.15 92.016,85.15 92.016,80.05 80.95,80.05
RoutingCorners [All] p0: scope1count=1 scope1_0_kind=Board scope1_0_value=Board scope2count=1 scope2_0_kind=Board scope2_0_value=Board commentlength=0 cornerstyle=45-Degree minsetback=0.05 maxsetback=0.05
RoutingCorners [All] p1: cornerstyle=45-Degree minsetback=0.05 maxsetback=0.05
RoutingLayers [All] p0: scope1count=1 scope1_0_kind=Board scope1_0_value=Board scope2count=1 scope2_0_kind=Board scope2_0_value=Board commentlength=0 top layer=Automatic mid layer 1=Automatic mid layer 2=Automatic bottom layer=Automatic
RoutingPriority [All] p0: scope1count=1 scope1_0_kind=Board scope1_0_value=Board scope2count=1 scope2_0_kind=Board scope2_0_value=Board commentlength=0
RoutingTopology [All] p0: scope1count=1 scope1_0_kind=Board scope1_0_value=Board scope2count=1 scope2_0_kind=Board scope2_0_value=Board commentlength=0 topology=Shortest
RoutingVias [All] p0: scope1count=1 scope1_0_kind=Board scope1_0_value=Board scope2count=1 scope2_0_kind=Board scope2_0_value=Board commentlength=0 holewidth=0.4 width=0.8 viastyle="Through Hole" minholewidth=0.4 minwidth=0.8 maxholewidth=0.4 maxwidth=0.8
RoutingVias [All] p1: holewidth=0.4 width=0.8 viastyle="Through Hole" minholewidth=0.4 minwidth=0.8 maxholewidth=0.4 maxwidth=0.8
ShortCircuit [All] p0: scope1count=1 scope1_0_kind=Board scope1_0_value=Board scope2count=1 scope2_0_kind=Board scope2_0_value=Board commentlength=0 allowed=FALSE
SilkToBoardRegionClearance [All] p0: scope1count=1 scope1_0_kind=Board scope1_0_value=Board scope2count=1 scope2_0_kind=Board scope2_0_value=Board commentlength=0
SilkToSilkClearance [All] p0: scope1count=1 scope1_0_kind=Board scope1_0_value=Board scope2count=1 scope2_0_kind=Board scope2_0_value=Board commentlength=0
SilkToSilkClearance [All] p1: silktosilkclearance=0.1
SilkToSolderMaskClearance [All] p0 off: scope1count=1 scope1_0_kind=Board scope1_0_value=Board scope2count=1 scope2_0_kind=Board scope2_0_value=Board commentlength=44 // Protel DXP Scope 1 Expression Was: IsPad
SilkToSolderMaskClearance [IsPad] p1: minsilkscreentomaskgap=0.1 clearancetoexposedcopper=TRUE
SolderMaskExpansion [All] p0: scope1count=1 scope1_0_kind=Board scope1_0_value=Board scope2count=1 scope2_0_kind=Board scope2_0_value=Board commentlength=0 expansion=0.102
SolderMaskExpansion [All] p1: expansion=0.102
UnRoutedNet [All] p0: scope1count=1 scope1_0_kind=Board scope1_0_value=Board scope2count=1 scope2_0_kind=Board scope2_0_value=Board commentlength=0
UnpouredPolygon [All] p0: scope1count=1 scope1_0_kind=Board scope1_0_value=Board scope2count=1 scope2_0_kind=Board scope2_0_value=Board commentlength=0
Width [All] p0: scope1count=1 scope1_0_kind=Board scope1_0_value=Board scope2count=1 scope2_0_kind=Board scope2_0_value=Board commentlength=0 maxlimit=2 minlimit=0.2 preferedwidth=0.3
Width [All] p1: maxlimit=2 minlimit=0.2 preferedwidth=0.3
24 further rules are at their usual default settings.

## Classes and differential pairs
channel class RD238-02-TLP5222_DRIVER_VERA: 1 2 3 4 5 6 7
channel class RD238-01-IF_VERA: 1 2 3 4 5 6 7
component class RD238-00-TOP_BLOCK_VERB: C10 CN10 CN11 CN12 CN13 CN14 CN15 CN16 CN17 CN18 CN19 CN20 CN21 CN22 CN23 CN24 CN25 CN26 D10 D11 D12 D13 R10 R11 R12 R13 TP10 TP11 TP12 TP13 TP14 TP15 TP16 TP17 TP18 TP19 TP20 TP21 TP22 TP23 TP24 TP25 TP26 TP27 TP28 TP29 TP30 TP31 TP32 TP33 TP34 TP35 TP36 TP37
component class 1: C80 C81 C82 C83 C84 C85 L80 R80 R81 R82 R83 TP80 U80
component class 1: C50 C51 C52 C53 C54 C55 C56 C57 C58 C59 C60 C61 C62 C63 C64 C65 C66 C67 C68 C69 C70 C71 C72 C73 C74 C75 C76 C77 C78 C79 D50 D51 D52 D53 D54 D55 D56 D57 D58 D59 Q50 R50 R51 R52 R53 R54 R55 R56 R57 R58 R59 R60 R61 R62 R75 R76 R77 R78 T50 U50
component class 7: C307 C317 C327 C337 C347 C357 C367 C377 C387 D307 D317 D327 D337 D347 D357 D367 D377 R307 R317 R327 R337 R347 R357 R367 R377 R387 R397 R407 U307
component class 6: C306 C316 C326 C336 C346 C356 C366 C376 C386 D306 D316 D326 D336 D346 D356 D366 D376 R306 R316 R326 R336 R346 R356 R366 R376 R386 R396 R406 U306
component class 5: C305 C315 C325 C335 C345 C355 C365 C375 C385 D325 D335 D345 D355 D365 D375 R305 R315 R325 R335 R345 R355 R365 R375 R385 R395 R405 U305
component class 4: C304 C314 C324 C334 C344 C354 C364 C374 C384 D304 D314 D324 D334 D344 D354 D364 D374 R304 R314 R324 R334 R344 R354 R364 R374 R384 R394 R404 U304
component class 3: C303 C313 C323 C333 C343 C353 C363 C373 C383 D303 D313 D323 D333 D343 D353 D363 D373 R303 R313 R323 R333 R343 R353 R363 R373 R383 R393 R403 U303
component class 2: C302 C312 C322 C332 C342 C352 C362 C372 C382 D302 D312 D322 D332 D342 D352 D362 D372 R302 R312 R322 R332 R342 R352 R362 R372 R382 R392 R402 U302
component class 1: C301 C311 C321 C331 C341 C351 C361 C371 C381 D301 D311 D321 D331 D341 D351 D361 D371 R301 R311 R321 R331 R341 R351 R361 R371 R381 R391 R401 U301
component class 7: C207 C217 C247 D207 Q207 R207 R217 R227 R237 R247 R257 U207
component class 6: C206 C216 C226 C236 C246 D206 Q206 R2_6 R206 R216 R236 R246 R256 U206
component class 5: C245 D205 R205 R245 R255
component class 4: C204 C214 C224 C234 C244 D204 Q204 R204 R214 R224 R234 R244 R254 U204
component class 2: C202 C212 C222 C232 C242 D202 Q202 R202 R212 R222 R232 R242 R252 U202

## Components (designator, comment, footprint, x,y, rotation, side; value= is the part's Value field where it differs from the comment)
C10 "" 1608 80.5,54.15 r0 bottom
C50 "10 μ" 2012 69.85,50 r90 bottom
C51 "1000 p" 1608 85.9,50.9 r90 bottom
C52 "10 μ" 2012 68.25,50 r90 bottom
C53 "1 μ" 1608 87.2,50 r90 bottom
C54 "1000 p" 1608 82.85,47.25 r180 bottom
C55 "470 p" 1608 73.6,51.25 r270 bottom
C56 "10 μ" 2012 57.4,66.55 r180 top
C57 "10 μ" 2012 48.8,44.85 r270 top
C58 "10 μ" 2012 63.05,30.15 r180 top
C59 "10 μ" 2012 75.35,33 r180 top
C60 "10 μ" 2012 57.4,68.25 r180 top
C61 "10 μ" 2012 47.1,44.85 r270 top
C62 "10 μ" 2012 63.05,28.4 r180 top
C63 "10 μ" 2012 75.35,31.3 r180 top
C64 "0.1 μ" 1608 57.2,74 r180 top
C65 "0.1 μ" 1608 61.05,73.2 r90 top
C66 "0.1 μ" 1608 41.8,42.6 r270 top
C67 "0.1 μ" 1608 42.2,46 r270 top
C68 "0.1 μ" 1608 58.6,24.4 r90 top
C69 "0.1 μ" 1608 63.25,23.2 r180 top
C70 "0.1 μ" 1608 75.15,26.15 r180 top
C71 "0.1 μ" 1608 79.75,27.3 r270 top
C72 "47 μ" SMD 58.4,77.7 r0 top
C73 "47 μ" SMD 69.05,74.85 r0 top
C74 "47 μ" SMD 37.7,43.6 r90 top
C75 "47 μ" SMD 40.7,50.8 r0 top
C76 "47 μ" SMD 54.75,21.4 r270 top
C77 "47 μ" SMD 61.8,19.35 r0 top
C78 "47 μ" SMD 72.9,22.55 r0 top
C79 "47 μ" SMD 84.6,26.2 r0 top
C80 "1000 p" 1608 82.85,52.95 r0 top
C81 "0.1 μ" 1608 78.8,48.1 r90 top
C82 "4.7 μ" 2012 83,54.4 r0 top
C83 "4.7 μ" 2012 83,56 r0 top
C84 "22 μ" 2012 83.45,45.95 r0 top
C85 "22 μ" 2012 83.45,47.55 r0 top
C201 "" 1608 18.6,53.85 r0 bottom (schematic designator C20)
C202 "" 1608 49.35,3.9 r180 bottom (schematic designator C20)
C203 "" 1608 83.05,3.9 r180 bottom (schematic designator C20)
C204 "" 1608 59.9,94.7 r270 bottom (schematic designator C20)
C205 "" 1608 37.2,94.65 r270 bottom (schematic designator C20)
C206 "" 1608 86.45,93.15 r180 bottom (schematic designator C20)
C207 "" 1608 20.95,95.45 r270 bottom (schematic designator C20)
C211 "" 1608 18.6,55.8 r0 bottom (schematic designator C21)
C212 "" 1608 47.6,6.2 r270 bottom (schematic designator C21)
C213 "" 1608 81.35,6.2 r270 bottom (schematic designator C21)
C214 "" 1608 62.85,95.85 r270 bottom (schematic designator C21)
C215 "" 1608 39.8,95.85 r270 bottom (schematic designator C21)
C216 "" 1608 84.45,95.85 r270 bottom (schematic designator C21)
C217 "" 1608 26,96.55 r180 bottom (schematic designator C21)
C221 "" 1608 27.1,54.55 r180 bottom (schematic designator C22)
C222 "" 1608 53.7,4 r180 bottom (schematic designator C22)
C223 "" 1608 87.4,4 r180 bottom (schematic designator C22)
C224 "" 1608 68.65,96.2 r180 bottom (schematic designator C22)
C225 "" 1608 45.35,96.2 r180 bottom (schematic designator C22)
C226 "" 1608 90.25,96.2 r180 bottom (schematic designator C22)
C227 "" 1608 30.55,96.2 r180 bottom (schematic designator C22)
C231 "0.1 μ" 1608 27.1,53.15 r180 bottom (schematic designator C23)
C232 "0.1 μ" 1608 53.7,5.4 r180 bottom (schematic designator C23)
C233 "0.1 μ" 1608 87.4,5.4 r180 bottom (schematic designator C23)
C234 "0.1 μ" 1608 68.65,94.8 r180 bottom (schematic designator C23)
C235 "0.1 μ" 1608 45.35,94.8 r180 bottom (schematic designator C23)
C236 "0.1 μ" 1608 90.25,94.8 r180 bottom (schematic designator C23)
C237 "0.1 μ" 1608 30.55,94.8 r180 bottom (schematic designator C23)
C241 "" 1608 18.45,55 r0 top (schematic designator C24)
C242 "" 1608 52.35,4.85 r180 top (schematic designator C24)
C243 "" 1608 86.05,4.85 r180 top (schematic designator C24)
C244 "" 1608 60.15,95.25 r0 top (schematic designator C24)
C245 "" 1608 36.3,95.25 r0 top (schematic designator C24)
C246 "" 1608 81.75,95.25 r0 top (schematic designator C24)
C247 "" 1608 22,95.25 r0 top (schematic designator C24)
C301 "1000 p" 1608 23.95,55 r180 top (schematic designator C30)
C302 "1000 p" 1608 46.85,4.5 r0 top (schematic designator C30)
C303 "1000 p" 1608 80.6,4.5 r0 top (schematic designator C30)
C304 "1000 p" 1608 65.6,95.6 r180 top (schematic designator C30)
C305 "1000 p" 1608 42.6,95.6 r180 top (schematic designator C30)
C306 "1000 p" 1608 87.2,95.6 r180 top (schematic designator C30)
C307 "1000 p" 1608 28.3,95.6 r180 top (schematic designator C30)
C311 "0.1 μ" 1608 27.05,54.95 r0 top (schematic designator C31)
C312 "0.1 μ" 1608 43.65,4.5 r180 top (schematic designator C31)
C313 "0.1 μ" 1608 77.35,4.5 r180 top (schematic designator C31)
C314 "0.1 μ" 1608 68.85,95.6 r0 top (schematic designator C31)
C315 "0.1 μ" 1608 45.55,95.6 r0 top (schematic designator C31)
C316 "0.1 μ" 1608 90.45,95.6 r0 top (schematic designator C31)
C317 "0.1 μ" 1608 31.25,95.6 r0 top (schematic designator C31)
C321 "1 μ" 1608 28.35,41.4 r180 top (schematic designator C32)
C322 "1 μ" 1608 42.4,19.2 r0 top (schematic designator C32)
C323 "1 μ" 1608 74.3,17.35 r0 top (schematic designator C32)
C324 "1 μ" 1608 70.375,81.1 r180 top (schematic designator C32)
C325 "1 μ" 1608 45,79.3 r180 top (schematic designator C32)
C326 "1 μ" 1608 90.65,79.3 r180 top (schematic designator C32)
C327 "1 μ" 1608 30.95,79.3 r180 top (schematic designator C32)
C331 "1 μ" 1608 21.725,39.6 r0 top (schematic designator C33)
C332 "1 μ" 1608 48.2,19.2 r180 top (schematic designator C33)
C333 "1 μ" 1608 81.6,19.45 r180 top (schematic designator C33)
C334 "1 μ" 1608 64.55,81.1 r0 top (schematic designator C33)
C335 "1 μ" 1608 39.4,79.3 r0 top (schematic designator C33)
C336 "1 μ" 1608 84.8,79.3 r0 top (schematic designator C33)
C337 "1 μ" 1608 25.1,79.3 r0 top (schematic designator C33)
C341 "1 μ" 1608 24.85,40.2 r0 top (schematic designator C34)
C342 "1 μ" 1608 45.5,19.2 r180 top (schematic designator C34)
C343 "1 μ" 1608 78.5,19.45 r180 top (schematic designator C34)
C344 "1 μ" 1608 67.4,81.1 r0 top (schematic designator C34)
C345 "1 μ" 1608 42.275,79.3 r0 top (schematic designator C34)
C346 "1 μ" 1608 87.675,79.3 r0 top (schematic designator C34)
C347 "1 μ" 1608 27.975,79.3 r0 top (schematic designator C34)
C351 "10 μ" 2012 28.15,39.8 r180 top (schematic designator C35)
C352 "10 μ" 2012 42.15,20.8 r0 top (schematic designator C35)
C353 "10 μ" 2012 74.95,18.8 r0 top (schematic designator C35)
C354 "10 μ" 2012 70.3,79.55 r180 top (schematic designator C35)
C355 "10 μ" 2012 45.175,77.75 r180 top (schematic designator C35)
C356 "10 μ" 2012 90.575,77.75 r180 top (schematic designator C35)
C357 "10 μ" 2012 30.875,77.75 r180 top (schematic designator C35)
C361 "10 μ" 2012 21,37.7 r0 top (schematic designator C36)
C362 "10 μ" 2012 48.8,20.8 r180 top (schematic designator C36)
C363 "10 μ" 2012 81.9,20.9 r180 top (schematic designator C36)
C364 "10 μ" 2012 64.1,79.55 r0 top (schematic designator C36)
C365 "10 μ" 2012 38.975,77.75 r0 top (schematic designator C36)
C366 "10 μ" 2012 84.375,77.75 r0 top (schematic designator C36)
C367 "10 μ" 2012 24.675,77.75 r0 top (schematic designator C36)
C371 "10 μ" 2012 24.3,38.15 r0 top (schematic designator C37)
C372 "10 μ" 2012 45.35,20.8 r180 top (schematic designator C37)
C373 "10 μ" 2012 78.65,20.9 r180 top (schematic designator C37)
C374 "10 μ" 2012 67.2,79.55 r0 top (schematic designator C37)
C375 "10 μ" 2012 42.075,77.75 r0 top (schematic designator C37)
C376 "10 μ" 2012 87.475,77.75 r0 top (schematic designator C37)
C377 "10 μ" 2012 27.775,77.75 r0 top (schematic designator C37)
C381 "100 p" 1608 27.95,41.25 r270 bottom (schematic designator C38)
C382 "100 p" 1608 42.9,19.65 r90 bottom (schematic designator C38)
C383 "100 p" 1608 76.6,19.65 r90 bottom (schematic designator C38)
C384 "100 p" 1608 68.4,80.35 r270 bottom (schematic designator C38)
C385 "100 p" 1608 44.571,79.5 r270 bottom (schematic designator C38)
C386 "100 p" 1608 90.05,79.5 r270 bottom (schematic designator C38)
C387 "100 p" 1608 30.35,79.5 r270 bottom (schematic designator C38)
CN10 "XW4M-02D1-V1DS" XW4M-02D1-V1DS 93.75,50 r90 top
CN11 "XG4A-2632" XG4A-2632 7.1,34.76 r90 top
CN12 "NTC" 62300421021 76.45,93.75 r270 bottom
CN13 "DESAT_TOPU" 62300421021 20.1,30 r270 bottom
CN14 "DESAT_BOTU" 62300421021 64.9,67.05 r90 bottom
CN15 "GS_BOTU" 62300421021 69.735,72.85 r90 bottom
CN16 "GS_TOPU" 62300421021 29.55,30 r270 bottom
CN17 "DESAT_BOTV" 62300421021 38.5,67.05 r90 bottom
CN18 "GS_TOPV" 62300421021 62.4,30 r270 bottom
CN19 "GS_BOTV" 62300421021 43.935,72.85 r90 bottom
CN20 "DESAT_TOPV" 62300421021 50.15,30.5 r270 bottom
CN21 "DESAT_TOPW" 62300421021 84,34.65 r270 bottom
CN22 "DESAT_BOTW" 62300421021 83.9,67.05 r90 bottom
CN23 "GS_BOTW" 62300421021 84.25,72.85 r90 bottom
CN24 "GS_TOPW" 62300421021 75.1,30.7 r270 bottom
CN25 "DESAT_BR" 62300421021 25.5,67.05 r90 bottom
CN26 "GS_BR" 62300421021 33.95,72.85 r90 bottom
D10 "" ESC 4.3,78.5 r0 top
D11 "" ESC 11.65,56.55 r270 bottom
D12 "" ESC 12.15,54.8 r90 top
D13 "" S-FLAT 88.7,49.8 r90 bottom
D50 "CRZ33" S-FLAT 77.7,53.25 r0 top
D51 "CUHS10F60" SOD-323HE 78.6,56 r90 top
D52 "CRH01" S-FLAT 55.4,62.95 r90 top
D53 "CRH01" S-FLAT 47.05,40.55 r180 top
D54 "CRH01" S-FLAT 60,31.5 r270 top
D55 "CRH01" S-FLAT 69.9,31 r270 top
D56 "CRZ16" S-FLAT 56.7,72.3 r180 top
D57 "CRZ16" S-FLAT 43.4,42.2 r270 top
D58 "CRZ16" S-FLAT 60.4,24.75 r90 top
D59 "CRZ16" S-FLAT 75.55,27.65 r180 top
D201 "" ESC 11.65,53.4 r90 bottom (schematic designator D20)
D202 "" ESC 7.6,19.85 r180 bottom (schematic designator D20)
D203 "" ESC 4.05,19.85 r0 bottom (schematic designator D20)
D204 "" ESC 5.35,88 r180 bottom (schematic designator D20)
D205 "" ESC 2.4,88 r0 bottom (schematic designator D20)
D206 "" ESC 3.1,84 r90 bottom (schematic designator D20)
D207 "" ESC 2.55,83.1 r0 top (schematic designator D20)
D301 "CUZ8V2" ESC 30.7,41.15 r270 bottom (schematic designator D30)
D302 "CUZ8V2" ESC 44.4,19.75 r90 bottom (schematic designator D30)
D303 "CUZ8V2" ESC 78.1,19.75 r90 bottom (schematic designator D30)
D304 "CUZ8V2" ESC 67.1,80.25 r270 bottom (schematic designator D30)
D305 "CUZ8V2" ESC 43.35,79.4 r270 bottom (schematic designator D30)
D306 "CUZ8V2" ESC 88.75,79.4 r270 bottom (schematic designator D30)
D307 "CUZ8V2" ESC 29.05,79.4 r270 bottom (schematic designator D30)
D311 "CUS05F30" ESC 29.4,41.15 r90 bottom (schematic designator D31)
D312 "CUS05F30" ESC 46,19.75 r270 bottom (schematic designator D31)
D313 "CUS05F30" ESC 79.7,19.75 r270 bottom (schematic designator D31)
D314 "CUS05F30" ESC 65.8,80.25 r90 bottom (schematic designator D31)
D315 "CUS05F30" ESC 41.971,79.4 r90 bottom (schematic designator D31)
D316 "CUS05F30" ESC 87.35,79.4 r90 bottom (schematic designator D31)
D317 "CUS05F30" ESC 27.65,79.4 r90 bottom (schematic designator D31)
D321 "CRF03A" S-FLAT 17.85,20.65 r90 bottom (schematic designator D32)
D322 "CRF03A" S-FLAT 36.2,29.3 r90 bottom (schematic designator D32)
D323 "CRF03A" S-FLAT 93.3,33.75 r90 bottom (schematic designator D32)
D324 "CRF03A" S-FLAT 75.35,66.35 r180 bottom (schematic designator D32)
D325 "CRF03A" S-FLAT 49.55,66.45 r180 bottom (schematic designator D32)
D326 "CRF03A" S-FLAT 94.95,66.35 r180 bottom (schematic designator D32)
D327 "CRF03A" S-FLAT 16.4,67.9 r270 bottom (schematic designator D32)
D331 "CRF03A" S-FLAT 17.85,15.7 r90 bottom (schematic designator D33)
D332 "CRF03A" S-FLAT 36.2,24.8 r90 bottom (schematic designator D33)
D333 "CRF03A" S-FLAT 93.3,29.25 r90 bottom (schematic designator D33)
D334 "CRF03A" S-FLAT 76.75,69.45 r270 bottom (schematic designator D33)
D335 "CRF03A" S-FLAT 50.95,69.55 r270 bottom (schematic designator D33)
D336 "CRF03A" S-FLAT 96.35,69.45 r270 bottom (schematic designator D33)
D337 "CRF03A" S-FLAT 16.4,72.4 r270 bottom (schematic designator D33)
D341 "CRF03A" S-FLAT 21.75,14.05 r180 bottom (schematic designator D34)
D342 "CRF03A" S-FLAT 36.2,20.3 r90 bottom (schematic designator D34)
D343 "CRF03A" S-FLAT 93.3,24.75 r90 bottom (schematic designator D34)
D344 "CRF03A" S-FLAT 76.75,73.95 r270 bottom (schematic designator D34)
D345 "CRF03A" S-FLAT 50.95,74.05 r270 bottom (schematic designator D34)
D346 "CRF03A" S-FLAT 96.35,73.95 r270 bottom (schematic designator D34)
D347 "CRF03A" S-FLAT 16.4,76.9 r270 bottom (schematic designator D34)
D351 "CRF03A" S-FLAT 26.7,14.05 r180 bottom (schematic designator D35)
D352 "CRF03A" S-FLAT 36.2,15.8 r90 bottom (schematic designator D35)
D353 "CRF03A" S-FLAT 93.3,20.25 r90 bottom (schematic designator D35)
D354 "CRF03A" S-FLAT 76.75,78.45 r270 bottom (schematic designator D35)
D355 "CRF03A" S-FLAT 50.95,78.55 r270 bottom (schematic designator D35)
D356 "CRF03A" S-FLAT 96.35,78.45 r270 bottom (schematic designator D35)
D357 "CRF03A" S-FLAT 16.4,81.4 r270 bottom (schematic designator D35)
D361 "CUHS10F60" SOD-323HE 23.05,37.8 r0 bottom (schematic designator D36)
D362 "CUHS10F60" SOD-323HE 59.55,18.2 r0 bottom (schematic designator D36)
D363 "CUHS10F60" SOD-323HE 79.85,24.65 r180 bottom (schematic designator D36)
D364 "CUHS10F60" SOD-323HE 59.6,76.5 r270 bottom (schematic designator D36)
D365 "CUHS10F60" SOD-323HE 35.6,77.4 r270 bottom (schematic designator D36)
D366 "CUHS10F60" SOD-323HE 81.05,78.45 r270 bottom (schematic designator D36)
D367 "CUHS10F60" SOD-323HE 21.35,75.8 r270 bottom (schematic designator D36)
D371 "MMSZ4678-HF" SOD-123 17.95,25.8 r90 bottom (schematic designator D37)
D372 "MMSZ4678-HF" SOD-123 42,30.7 r0 bottom (schematic designator D37)
D373 "MMSZ4678-HF" SOD-123 90.1,35.15 r180 bottom (schematic designator D37)
D374 "MMSZ4678-HF" SOD-123 70.75,66.45 r180 bottom (schematic designator D37)
D375 "MMSZ4678-HF" SOD-123 44.65,66.45 r180 bottom (schematic designator D37)
D376 "MMSZ4678-HF" SOD-123 90.05,66.45 r180 bottom (schematic designator D37)
D377 "MMSZ4678-HF" SOD-123 19.6,66.5 r0 bottom (schematic designator D37)
L80 "4.7 μH" 4020 87.3,48.85 r270 top
Q50 "SSM6K819R" TSOP6F 76.35,51.45 r180 bottom
Q201 "" SSM 24.65,56.75 r90 bottom (schematic designator Q20)
Q202 "" SSM 57.05,4.6 r180 top (schematic designator Q20)
Q203 "" SSM 89.35,6.35 r180 top (schematic designator Q20)
Q204 "" SSM 55.45,95.5 r0 top (schematic designator Q20)
Q205 "" SSM 33.8,95.85 r180 bottom (schematic designator Q20)
Q206 "" SSM 77.05,95.5 r0 top (schematic designator Q20)
Q207 "" SSM 17.55,94 r270 top (schematic designator Q20)
R10 "0" 1608 4.3,80.1 r180 top
R11 "0" 1608 86.65,44.35 r0 top
R12 "4.7 k" 1608 13.05,56.6 r90 bottom
R13 "4.7 k" 1608 14.2,53.95 r180 top
R50 "330 k" 1608 84.35,52.95 r0 bottom
R51 "33 k" 1608 83.7,50.95 r90 bottom
R52 "100 k" 1608 78.5,54.6 r270 bottom
R53 "39" 1608 72.25,51.25 r90 bottom
R54 "4.7 k" 1608 77.2,54.6 r90 bottom
R55 "0" 1608 77.9,49.05 r0 bottom
R56 "0" 1608 75.9,47.05 r0 bottom
R57 "10m" 2012 74.15,48.7 r0 bottom
R58 "10m" 2012 71,47.5 r0 bottom
R59 "2.2 k" 2012 57.4,69.95 r180 top
R60 "2.2 k" 2012 45.4,44.85 r270 top
R61 "2.2 k" 2012 63.05,26.7 r180 top
R62 "2.2 k" 2012 75.35,29.6 r180 top
R75 "820" 1608 59.75,73.2 r90 top
R76 "820" 1608 43.5,46 r270 top
R77 "820" 1608 63.25,24.5 r180 top
R78 "820" 1608 78.45,27.3 r270 top
R80 "15 k" 1608 76.2,50.8 r90 top
R81 "82 k" 1608 76.2,48.1 r90 top
R82 "12 k" 1608 77.5,50.8 r90 top
R83 "1.2 k" 1608 77.5,48.1 r90 top
R201 "4.7 k" 1608 13.05,53.25 r270 bottom (schematic designator R20)
R202 "4.7 k" 1608 7.7,18 r0 bottom (schematic designator R20)
R203 "4.7 k" 1608 3.95,18 r180 bottom (schematic designator R20)
R204 "4.7 k" 1608 5.45,89.4 r0 bottom (schematic designator R20)
R205 "4.7 k" 1608 2.35,89.4 r180 bottom (schematic designator R20)
R206 "4.7 k" 1608 4.5,84.5 r270 bottom (schematic designator R20)
R207 "4.7 k" 1608 2.45,84.5 r180 top (schematic designator R20)
R211 "" 1608 18.6,52.55 r180 bottom (schematic designator R21)
R212 "" 1608 46.45,3.9 r180 bottom (schematic designator R21)
R213 "" 1608 80.15,3.9 r180 bottom (schematic designator R21)
R214 "" 1608 57.35,94.3 r180 bottom (schematic designator R21)
R215 "" 1608 34.7,93.85 r180 bottom (schematic designator R21)
R216 "" 1608 83.65,93.15 r180 bottom (schematic designator R21)
R217 "" 1608 18.75,94.7 r180 bottom (schematic designator R21)
R221 "" 1608 18.6,57.1 r180 bottom (schematic designator R22)
R222 "" 1608 45.35,5.45 r180 bottom (schematic designator R22)
R223 "" 1608 79.15,5.45 r180 bottom (schematic designator R22)
R224 "" 1608 61.35,95.85 r90 bottom (schematic designator R22)
R225 "" 1608 38.5,95.85 r90 bottom (schematic designator R22)
R226 "" 1608 82.95,95.85 r90 bottom (schematic designator R22)
R227 "" 1608 23.25,96.1 r180 bottom (schematic designator R22)
R231 "" 1608 24.35,54.7 r0 bottom (schematic designator R23)
R232 "" 1608 59.3,4.55 r270 top (schematic designator R23)
R233 "" 1608 91.55,6.35 r270 top (schematic designator R23)
R234 "" 1608 53.2,95.55 r90 top (schematic designator R23)
R235 "" 1608 35.9,95.85 r90 bottom (schematic designator R23)
R236 "" 1608 74.8,95.55 r90 top (schematic designator R23)
R237 "" 1608 17.55,96.25 r0 top (schematic designator R23)
R241 "330" 1608 18.45,56.3 r180 top (schematic designator R24)
R242 "330" 1608 52.35,3.55 r0 top (schematic designator R24)
R243 "330" 1608 86.05,3.55 r0 top (schematic designator R24)
R244 "330" 1608 60.15,96.55 r180 top (schematic designator R24)
R245 "330" 1608 36.3,96.55 r180 top (schematic designator R24)
R246 "330" 1608 81.75,96.55 r180 top (schematic designator R24)
R247 "330" 1608 22,96.55 r180 top (schematic designator R24)
R251 "2.2 k" 1608 21.15,55 r180 top (schematic designator R25)
R252 "2.2 k" 1608 49.65,3.55 r0 top (schematic designator R25)
R253 "2.2 k" 1608 83.35,3.55 r0 top (schematic designator R25)
R254 "2.2 k" 1608 62.85,96.55 r180 top (schematic designator R25)
R255 "2.2 k" 1608 39.8,96.55 r180 top (schematic designator R25)
R256 "2.2 k" 1608 84.45,96.55 r180 top (schematic designator R25)
R257 "2.2 k" 1608 25.5,96.55 r180 top (schematic designator R25)
R301 "18 k" 1608 25.35,39.95 r270 bottom (schematic designator R30)
R302 "18 k" 1608 48,20.5 r180 bottom (schematic designator R30)
R303 "18 k" 1608 81.7,20.5 r180 bottom (schematic designator R30)
R304 "18 k" 1608 64.5,80.2 r270 bottom (schematic designator R30)
R305 "18 k" 1608 40.571,79.4 r270 bottom (schematic designator R30)
R306 "18 k" 1608 85.971,79.4 r270 bottom (schematic designator R30)
R307 "18 k" 1608 26.271,79.4 r270 bottom (schematic designator R30)
R311 "30 k" 1608 26.65,41.25 r90 bottom (schematic designator R31)
R312 "30 k" 1608 48,18.9 r180 bottom (schematic designator R31)
R313 "30 k" 1608 81.7,18.9 r180 bottom (schematic designator R31)
R314 "30 k" 1608 65.2,82.45 r0 bottom (schematic designator R31)
R315 "30 k" 1608 41.2,81.55 r0 bottom (schematic designator R31)
R316 "30 k" 1608 86.6,81.55 r0 bottom (schematic designator R31)
R317 "30 k" 1608 26.9,81.55 r0 bottom (schematic designator R31)
R321 "10" 2012 22.15,40.2 r90 bottom (schematic designator R32)
R322 "10" 2012 54.1,19.55 r180 bottom (schematic designator R32)
R323 "10" 2012 84.25,22.7 r270 bottom (schematic designator R32)
R324 "10" 2012 59.9,80.525 r90 bottom (schematic designator R32)
R325 "10" 2012 35.65,81.45 r90 bottom (schematic designator R32)
R326 "10" 2012 81.05,82.6 r90 bottom (schematic designator R32)
R327 "10" 2012 21.35,79.95 r90 bottom (schematic designator R32)
R331 "10" 2012 23.75,40.2 r90 bottom (schematic designator R33)
R332 "10" 2012 54.1,17.85 r180 bottom (schematic designator R33)
R333 "10" 2012 82.6,22.7 r270 bottom (schematic designator R33)
R334 "10" 2012 61.5,80.525 r90 bottom (schematic designator R33)
R335 "10" 2012 37.25,81.45 r90 bottom (schematic designator R33)
R336 "10" 2012 82.65,82.6 r90 bottom (schematic designator R33)
R337 "10" 2012 22.95,79.95 r90 bottom (schematic designator R33)
R341 "470" 1608 31.5,25.65 r90 bottom (schematic designator R34)
R342 "470" 1608 46.1,16 r0 bottom (schematic designator R34)
R343 "470" 1608 81.3,16 r180 bottom (schematic designator R34)
R344 "470" 1608 66.3,84.15 r180 bottom (schematic designator R34)
R345 "470" 1608 42.65,83.95 r180 bottom (schematic designator R34)
R346 "470" 1608 88.05,83.95 r180 bottom (schematic designator R34)
R347 "470" 1608 26.85,84.15 r0 bottom (schematic designator R34)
